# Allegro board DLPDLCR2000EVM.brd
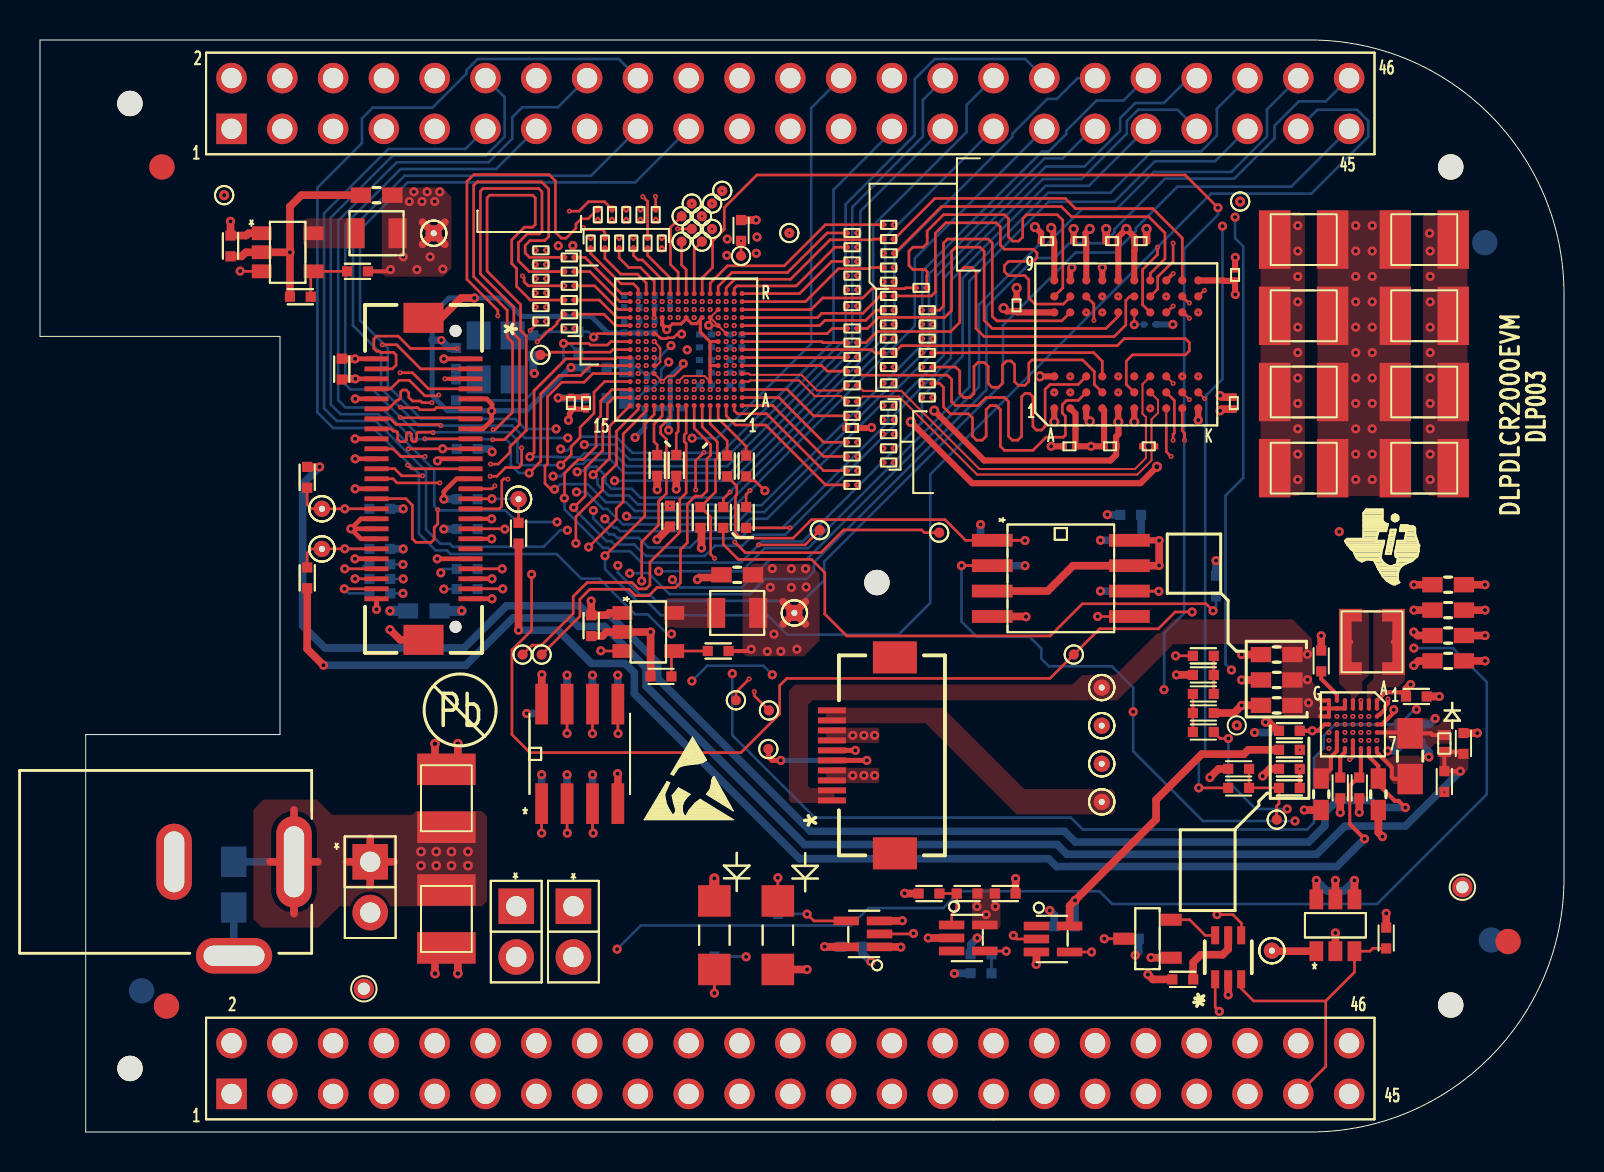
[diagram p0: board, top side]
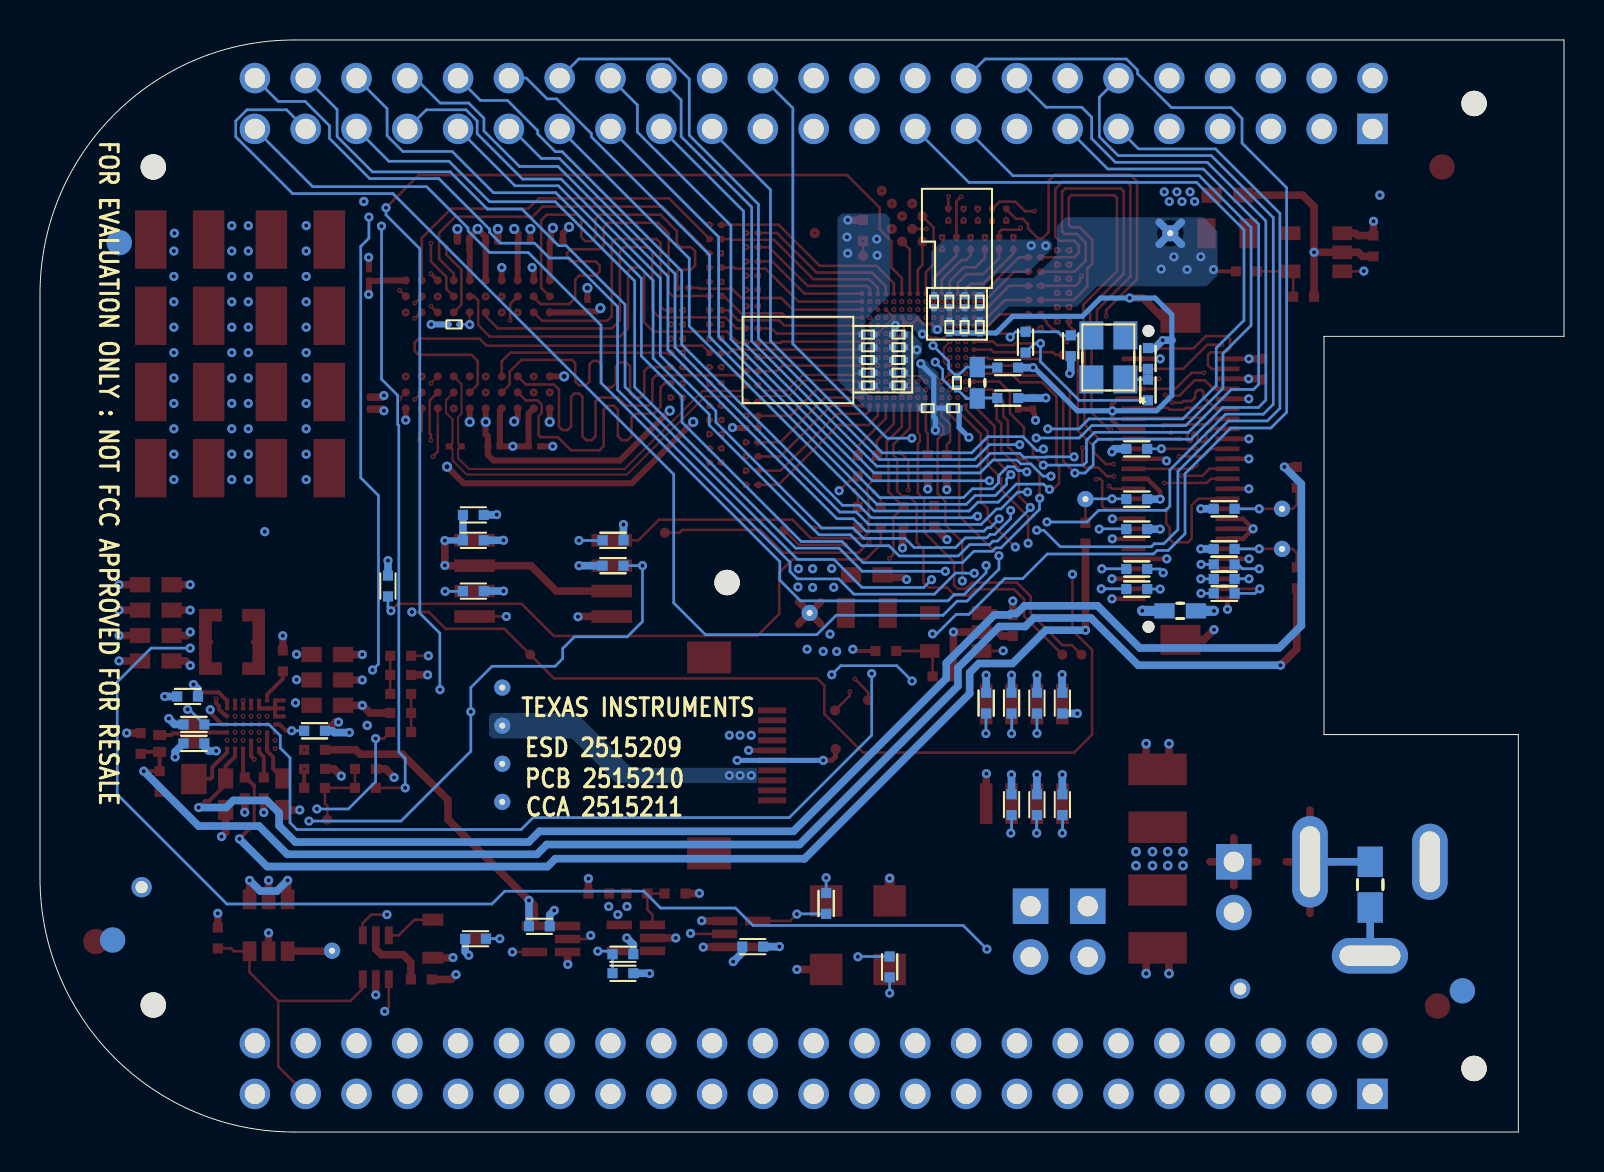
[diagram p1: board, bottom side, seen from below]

Outline 76.2 x 54.61 mm; copper layers: TOP, LY2, LY3, LY4, LY5, BOTTOM. Coordinates in mm from the lower left corner of the outline.
Outline path: 0,54.61 0,39.79 12,39.79 12,19.88 2.29,19.88 2.29,0 63.5,0 arc(72.48,3.72) 76.2,12.7 76.2,41.91 arc(72.48,50.89) 63.5,54.61 0,54.61

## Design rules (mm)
net group DMD_BUS: nets DMD_BUS DMD_BUS_T
net group DMD_D0: nets DMD_D0 DMD_D0_T
net group DMD_D1: nets DMD_D1 DMD_D1_T
net group DMD_D2: nets DMD_D2 DMD_D2_T
net group DMD_D3: nets DMD_D3 DMD_D3_T
net group DMD_D4: nets DMD_D4 DMD_D4_T
net group DMD_D5: nets DMD_D5 DMD_D5_T
net group DMD_D6: nets DMD_D6 DMD_D6_T
net group DMD_D7: nets DMD_D7 DMD_D7_T
net group DMD_D8: nets DMD_D8 DMD_D8_T
net group DMD_D9: nets DMD_D9 DMD_D9_T
net group DMD_D10: nets DMD_D10 DMD_D10_T
net group DMD_D11: nets DMD_D11 DMD_D11_T
net group DMD_D12: nets DMD_D12 DMD_D12_T
net group DMD_D13: nets DMD_D13 DMD_D13_T
net group DMD_D14: nets DMD_D14 DMD_D14_T
net group DMD_DCLK: nets DMD_DCLK DMD_DCLK_T
net group DMD_LOADB: nets DMD_LOADB DMD_LOADB_T
net group DMD_SAC_BUS: nets DMD_SAC_BUS DMD_SAC_BUS_T
net group DMD_SAC_CLK: nets DMD_SAC_CLK DMD_SAC_CLK_T
net group DMD_SCTRL: nets DMD_SCTRL DMD_SCTRL_T
net group DMD_STRB: nets DMD_STRB DMD_STRB_T
net group DMD_TRC: nets DMD_TRC DMD_TRC_T
net group MEM0_A0: nets MEM0_A0 MEM_T_A0
net group MEM0_A1: nets MEM0_A1 MEM_T_A1
net group MEM0_A2: nets MEM0_A2 MEM_T_A2
net group MEM0_A3: nets MEM0_A3 MEM_T_A3
net group MEM0_A4: nets MEM0_A4 MEM_T_A4
net group MEM0_A5: nets MEM0_A5 MEM_T_A5
net group MEM0_A6: nets MEM0_A6 MEM_T_A6
net group MEM0_A7: nets MEM0_A7 MEM_T_A7
net group MEM0_A8: nets MEM0_A8 MEM_T_A8
net group MEM0_A9: nets MEM0_A9 MEM_T_A9
net group MEM0_A10: nets MEM0_A10 MEM_T_A10
net group MEM0_A11: nets MEM0_A11 MEM_T_A11
net group MEM0_A12: nets MEM0_A12 MEM_T_A12
net group MEM0_BA0: nets MEM0_BA0 MEM_T_BA0
net group MEM0_BA1: nets MEM0_BA1 MEM_T_BA1
net group MEM0_CASZ: nets MEM0_CASZ MEM_T_CASZ
net group MEM0_CKE: nets MEM0_CKE MEM_T_CKE
net group MEM0_CLK_N: nets MEM0_CLK_N MEM_T_CLK_N
net group MEM0_CLK_P: nets MEM0_CLK_P MEM_T_CLK_P
net group MEM0_CSZ: nets MEM0_CSZ MEM_T_CSZ
net group MEM0_DQ0: nets MEM0_DQ0 MEM_T_DQ0
net group MEM0_DQ1: nets MEM0_DQ1 MEM_T_DQ1
net group MEM0_DQ2: nets MEM0_DQ2 MEM_T_DQ2
net group MEM0_DQ3: nets MEM0_DQ3 MEM_T_DQ3
net group MEM0_DQ4: nets MEM0_DQ4 MEM_T_DQ4
net group MEM0_DQ5: nets MEM0_DQ5 MEM_T_DQ5
net group MEM0_DQ6: nets MEM0_DQ6 MEM_T_DQ6
net group MEM0_DQ7: nets MEM0_DQ7 MEM_T_DQ7
net group MEM0_DQ8: nets MEM0_DQ8 MEM_T_DQ8
net group MEM0_DQ9: nets MEM0_DQ9 MEM_T_DQ9
net group MEM0_DQ10: nets MEM0_DQ10 MEM_T_DQ10
net group MEM0_DQ11: nets MEM0_DQ11 MEM_T_DQ11
net group MEM0_DQ12: nets MEM0_DQ12 MEM_T_DQ12
net group MEM0_DQ13: nets MEM0_DQ13 MEM_T_DQ13
net group MEM0_DQ14: nets MEM0_DQ14 MEM_T_DQ14
net group MEM0_DQ15: nets MEM0_DQ15 MEM_T_DQ15
net group MEM0_LDM: nets MEM0_LDM MEM_T_LDM
net group MEM0_LDQS: nets MEM0_LDQS MEM_T_LDQS
net group MEM0_RASZ: nets MEM0_RASZ MEM_T_RASZ
net group MEM0_UDM: nets MEM0_UDM MEM_T_UDM
net group MEM0_UDQS: nets MEM0_UDQS MEM_T_UDQS
net group MEM0_WEZ: nets MEM0_WEZ MEM_T_WEZ

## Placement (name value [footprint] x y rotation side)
C1  4.7uF  [0402]  9.53 44.31 90 top
C2  10uF  [0603]  16.83 46.85 180 top
C3  0.1uF  [0201]  50.36 44.55 0 top
C4  0.1uF  [0201]  51.98 44.55 0 top
C5  0.1uF  [0201]  53.61 44.55 0 top
C6  0.1uF  [0201]  55.03 44.55 180 top
C7  1uF  [0201]  59.75 42.86 270 top
C8  100uF  [1210]  63.18 44.63 180 top
C9  100uF  [1210]  69.22 44.63 0 top
C10  0.1uF  [0201]  48.83 41.34 270 top
C11  100uF  [1210]  63.18 40.82 180 top
C12  100uF  [1210]  69.22 40.82 0 top
C13  0.1uF  [0201]  26.54 36.45 90 top
C14  1uF  [0201]  27.3 36.45 90 top
C15  0.1uF  [0201]  51.47 34.29 0 top
C16  0.1uF  [0201]  53.51 34.29 180 top
C17  0.1uF  [0201]  59.69 36.45 90 top
C18  100uF  [1210]  63.18 37.01 180 top
C19  100uF  [1210]  69.22 37.01 0 top
C20  100uF  [1210]  63.18 33.2 180 top
C21  100uF  [1210]  69.22 33.2 0 top
C23  4.7uF  [0402]  27.56 25.32 90 top
C24  10uF  [0603]  34.86 27.86 180 top
C25  0.1uF  [0402_AVXA]  58.17 22.86 180 top
C26  10uF  [0603]  61.84 23.88 180 top
C27  0.1uF  [0402_AVXA]  64.06 23.56 270 top
C28  10uF  [0603]  70.41 27.37 0 top
C29  10uF  [0603]  70.41 26.1 0 top
C30  10uF  [0603]  70.41 24.83 0 top
C31  10uF  [0603]  70.41 23.56 0 top
C32  100uF  [1210]  20.32 16.69 270 top
C33  0.1uF  [0402_AVXA]  58.17 20.95 0 top
C34  10uF  [0603]  61.84 22.61 180 top
C35  10uF  [0603]  61.84 21.34 180 top
C36  1uF  [0402]  62.47 20.07 0 top
C37  0.01uF  [0402]  62.47 18.16 180 top
C38  2.2uF  [0402]  65.01 17.21 270 top
C39  1uF  [0402]  65.96 17.21 270 top
C40  1uF  [0603]  66.92 16.89 270 top
C41  0.1uF  [0402_AVXA]  68.82 21.78 0 top
C42  0.22uF  [0402]  71.17 19.43 90 top
C43  100uF  [1210]  20.32 10.66 90 top
C44  1uF  [0402]  48.26 11.93 0 top
C100  0.1uF  [0201]  34.8 39.88 180 bottom
C101  0.1uF  [0201]  34.8 39.24 180 bottom
C102  0.1uF  [0201]  33.27 39.88 0 bottom
C103  0.1uF  [0201]  33.27 39.24 0 bottom
C104  0.1uF  [0201]  31.5 41.53 270 bottom
C105  0.1uF  [0201]  30.73 41.53 270 bottom
C106  0.1uF  [0201]  30.73 40.26 90 bottom
C107  0.1uF  [0201]  29.97 41.53 270 bottom
C108  0.1uF  [0201]  29.97 40.26 90 bottom
C109  0.1uF  [0201]  29.21 41.53 270 bottom
C110  0.1uF  [0201]  29.21 40.26 90 bottom
C111  18pF  [0402]  24.66 39.32 90 bottom
C112  0.1uF  [0201]  34.8 38.61 180 bottom
C113  0.1uF  [0201]  34.8 37.97 180 bottom
C114  1uF  [0201]  34.8 37.34 180 bottom
C115  0.1uF  [0201]  33.27 38.61 0 bottom
C116  0.1uF  [0201]  33.27 37.97 0 bottom
C117  0.1uF  [0201]  33.27 37.34 0 bottom
C118  0.1uF  [0201]  31.81 36.2 180 bottom
C119  0.1uF  [0201]  30.54 36.2 0 bottom
C120  0.1uF  [0201]  30.35 37.47 270 bottom
C121  10uF  [0603]  29.34 37.47 270 bottom
C122  18pF  [0402]  20.8 38.68 90 bottom
C123  0.1uF  [0402_AVXA]  54.53 29.59 180 bottom
C124  0.1uF  [0402]  16.99 31.17 0 bottom
C125  0.1uF  [0402]  16.99 29.16 0 bottom
C126  0.1uF  [0402_AVXA]  15.09 38.15 270 top
C127  0.1uF  [0402]  21.36 31.65 180 bottom
C128  0.22uF  [0603]  19.19 26.06 180 bottom
C129  0.1uF  [0402_AVXA]  68.82 21.78 0 bottom
C130  0.1uF  [0402_AVXA]  68.5 19.43 0 bottom
C131  0.1uF  [0402_AVXA]  25.08 21.45 270 bottom
C132  0.1uF  [0402_AVXA]  51.23 10.29 180 bottom
C133  0.1uF  [0402_AVXA]  47.05 8.89 180 bottom
C134  0.1uF  [0402_AVXA]  40.56 9.27 0 bottom
D1  PMEG4002EL  [SOD882]  70.22 19.43 270 top
D2  green  [1206]  33.72 9.84 90 top
D3  green  [1206]  36.89 9.84 90 top
F100  BLM15PD800SN1D  [0402]  27.81 38.23 180 bottom
F101  BLM15PD800SN1D  [0402]  27.81 36.7 0 bottom
J1  PS-50028-05081-001  [CON_SMVT_50028-50]  19.18 32.66 270 top
J2  Pwr Jack, 2.1mm pin  [PJ-002A]  12.7 13.51 180 top
J3  HDR,2P,1R  [HDR2P_1R]  16.51 13.51 180 top
J4  HDR,2P,1R  [HDR2P_1R]  23.81 11.29 180 top
J5  HDR,2P,1R  [HDR2P_1R]  26.67 11.29 180 top
JLEDFLEX  EM,CONN,10P,ZIF  [CON_SMRT_52893-1095_NO-GND]  42.6 18.83 90 top
L1  2.2uH  [1008_2P5MMX2MM]  16.83 44.95 0 top
L2  2.2uH  [1008_2P5MMX2MM]  34.86 25.96 0 top
L3  2.2uH  [COILCRAFT_LPS3015]  66.6 24.51 180 top
L4  10uH  [0805]  68.5 18.8 90 top
NOREF  -  [unnamed]  70.54 48.26 0 top
NOREF#2  -  [#2]  32.69 17.4 0 top
NOREF#3  -  [#2]  2.29 0 90 top
NOREF#4  -  [unnamed]  6.32 6.3 0 top
NOREF#5  -  [unnamed]  4.5 3.18 0 top
NOREF#6  -  [unnamed]  6.1 48.26 0 top
NOREF#7  -  [#2]  0 54.61 0 top
NOREF#8  -  [#2]  0 54.61 0 top
NOREF#9  -  [#2]  67.16 29.51 0 top
NOREF#10  -  [#2]  -95.55 -48.74 0 top
NOREF#11  -  [unnamed]  70.54 6.35 0 top
NOREF#12  -  [#2]  -9.45 -48.23 0 top
NOREF#13  -  [unnamed]  4.5 51.44 0 top
NOREF#14  -  [#2]  2.29 0 0 top
NOREF#15  -  [#2]  2.29 0 90 top
NOREF#16  -  [#2]  96.9 37.47 0 top
NOREF#17  -  [#2]  71.96 51.38 0 top
NOREF#18  -  [#2]  2.29 0 90 top
NOREF#19  -  [unnamed]  41.85 27.48 0 top
NOREF#20  -  [#2]  2.29 0 90 top
NOREF#21  -  [#2]  2.29 0 0 top
NOREF#22  -  [unnamed]  73.41 9.53 0 top
NOREF#23  -  [unnamed]  72.57 9.6 180 bottom
NOREF#24  -  [unnamed]  5.08 7.06 180 bottom
NOREF#25  -  [unnamed]  72.24 44.48 180 bottom
P1  EM,HDR,46P,2R,2x  [PRT_12790]  9.58 50.16 90 top
P2  EM,HDR,46P,2R,2x  [PRT_12790]  9.58 1.91 90 top
R1  120k  [0402]  13.02 41.77 180 top
R2  82k  [0402]  15.88 43.04 0 top
R3  30  [0201_R]  25.04 44.09 0 top
R5  30  [0201_R]  25.04 43.38 0 top
R6  30  [0201_R]  25.04 42.67 0 top
R7  30  [0201_R]  25.04 41.96 0 top
R8  30  [0201_R]  26.47 43.74 0 top
R9  30  [0201_R]  26.47 43.03 0 top
R10  30  [0201_R]  26.47 42.32 0 top
R11  30  [0201_R]  26.47 41.61 0 top
R12  30  [0201_R]  27.53 44.45 270 top
R13  30  [0201_R]  27.89 45.87 270 top
R14  30  [0201_R]  28.24 44.45 270 top
R15  30  [0201_R]  28.6 45.87 270 top
R16  30  [0201_R]  28.96 44.45 270 top
R17  30  [0201_R]  29.31 45.87 270 top
R18  30  [0201_R]  29.67 44.45 270 top
R19  30  [0201_R]  30.02 45.87 270 top
R20  30  [0201_R]  30.38 44.45 270 top
R21  30  [0201_R]  30.78 45.87 270 top
R22  30  [0201_R]  31.09 44.45 270 top
R23  10k  [0402]  35.05 45.09 270 top
R24  30  [0201_R]  40.6 44.96 180 top
R25  30  [0201_R]  40.6 44.25 180 top
R26  30  [0201_R]  40.6 43.54 180 top
R27  30  [0201_R]  40.6 42.83 180 top
R28  30  [0201_R]  40.6 42.11 180 top
R29  30  [0201_R]  42.43 45.37 180 top
R30  30  [0201_R]  42.43 44.65 180 top
R31  30  [0201_R]  42.43 43.23 180 top
R32  30  [0201_R]  42.43 42.52 180 top
R33  30  [0201_R]  42.43 41.81 0 top
R34  30  [0201_R]  42.45 43.94 180 top
R35  30  [0201_R]  44.06 42.22 0 top
R36  30  [0201_R]  25.04 41.25 0 top
R37  30  [0201_R]  25.04 40.54 0 top
R38  30  [0201_R]  26.47 40.89 0 top
R39  30  [0201_R]  26.47 40.18 0 top
R40  30  [0201_R]  40.6 41.3 180 top
R41  30  [0201_R]  40.6 40.18 0 top
R42  30  [0201_R]  40.6 39.47 180 top
R43  30  [0201_R]  40.6 38.76 0 top
R44  30  [0201_R]  40.6 38.05 0 top
R45  30  [0201_R]  42.43 41.1 0 top
R46  30  [0201_R]  42.43 40.39 0 top
R47  30  [0201_R]  42.43 39.68 0 top
R48  30  [0201_R]  42.43 38.96 180 top
R49  30  [0201_R]  42.43 38.25 0 top
R50  30  [0201_R]  44.36 41.1 0 top
R51  30  [0201_R]  44.36 40.39 0 top
R52  30  [0201_R]  44.36 39.68 0 top
R53  30  [0201_R]  44.36 38.96 0 top
R54  30  [0201_R]  44.36 38.25 0 top
R55  30  [0201_R]  40.6 37.34 180 top
R56  30  [0201_R]  40.6 36.53 180 top
R57  30  [0201_R]  40.6 35.82 180 top
R58  10k  [0201]  40.6 35.21 0 top
R59  30  [0201_R]  40.6 34.49 180 top
R60  30  [0201_R]  42.43 37.44 0 top
R61  30  [0201_R]  42.43 36.32 0 top
R62  30  [0201_R]  42.43 35.61 180 top
R63  30  [0201_R]  42.43 34.9 180 top
R64  30  [0201_R]  42.43 34.19 180 top
R65  30  [0201_R]  44.36 37.44 0 top
R66  30  [0201_R]  44.36 36.73 0 top
R67  100  [0201]  55.44 34.29 180 top
R68  0  [0402]  13.36 32.74 270 top
R69  0  [0402]  13.36 27.71 90 top
R70  100k  [0402]  30.86 33.34 90 top
R71  10k  [0402]  31.5 30.8 270 top
R72  30.1  [0402]  31.81 33.34 270 top
R74  100k  [0402]  33.02 30.73 90 top
R75  30.1  [0402]  34.16 30.73 90 top
R76  30.1  [0402]  34.36 33.31 90 top
R77  30.1  [0402]  35.31 30.73 90 top
R78  30.1  [0402]  35.31 33.31 90 top
R79  30  [0201_R]  40.6 33.78 180 top
R80  30  [0201_R]  40.6 33.07 180 top
R81  30  [0201_R]  40.6 32.36 180 top
R82  30  [0201_R]  42.43 33.48 180 top
R83  180k  [0402]  31.05 22.78 180 top
R84  360k  [0402]  33.91 24.05 0 top
R85  1K  [0402]  58.17 23.81 0 top
R86  1K  [0402]  58.17 21.91 180 top
R87  1K  [0402]  58.17 20 0 top
R89  30.0k  [0402]  59.93 17.21 180 top
R90  0  [0402]  62.47 19.11 0 top
R91  0  [0402]  62.47 17.21 0 top
R92  0.10  [0603]  64.06 16.89 270 top
R93  100k  [0402]  70.22 17.53 270 top
R94  887k  [0402]  44.45 11.93 0 top
R95  953k  [0402]  46.36 11.93 0 top
R96  0  [0402]  57.14 7.63 180 top
R97  10k  [0402]  67.31 9.7 90 top
R100  30  [0201_R]  55.5 40.39 0 bottom
R101  953k  [0402]  26.92 39.5 270 bottom
R102  100  [0402]  20.8 37.11 90 bottom
R103  0  [0402]  54.53 30.86 0 bottom
R104  100k  [0402]  47.55 29.59 0 bottom
R105  0  [0402]  16.99 28.38 0 bottom
R106  0  [0402]  16.99 27.66 0 bottom
R107  0  [0402]  23.93 29.95 90 top
R108  100k  [0402]  21.36 30.15 180 bottom
R109  100k  [0402]  21.36 34.16 0 bottom
R110  100k  [0402]  58.8 27.3 270 bottom
R111  100k  [0402]  54.53 27.05 0 bottom
R112  100k  [0402]  47.55 28.32 180 bottom
R113  0  [0402]  16.99 26.94 0 bottom
R114  0  [0402]  21.36 28.16 0 bottom
R115  0  [0402]  21.36 27.15 0 bottom
R116  100k  [0402]  68.5 20.38 180 bottom
R117  0  [0402]  62.47 20.07 0 bottom
R118  5.6K  [0402]  28.89 21.45 90 bottom
R119  5.6K  [0402]  27.62 21.45 90 bottom
R120  0  [0402]  26.35 21.45 90 bottom
R121  4.75K  [0402]  27.62 16.37 90 bottom
R122  4.75K  [0402]  26.35 16.37 90 bottom
R123  4.75K  [0402]  25.08 16.37 90 bottom
R124  200  [0805]  9.69 12.37 270 bottom
R125  1K  [0402]  54.42 9.66 0 bottom
R126  100  [0402]  36.89 11.43 270 bottom
R128  0  [0402]  47.05 7.94 180 bottom
R129  100  [0402]  33.72 8.26 90 bottom
RT1  100k  [0402]  59.93 18.16 180 top
TP1  TP,20mil PAD  [20MIL_PAD]  9.21 46.85 0 top
TP2  TP,12mil Drill,32mil Pad  [HOLE_PLATED_12MIL_DRILL_32MIL_PAD]  19.69 44.95 0 top
TP3  TP,20mil PAD  [20MIL_PAD]  32.08 45.8 90 top
TP4  TP,20mil PAD  [20MIL_PAD]  32.08 44.53 90 top
TP5  TP,20mil PAD  [20MIL_PAD]  32.59 46.43 90 top
TP6  TP,20mil PAD  [20MIL_PAD]  32.59 45.16 90 top
TP7  TP,20mil PAD  [20MIL_PAD]  33.1 45.8 90 top
TP8  TP,20mil PAD  [20MIL_PAD]  33.1 44.53 90 top
TP9  TP,20mil PAD  [20MIL_PAD]  33.6 46.43 90 top
TP10  TP,20mil PAD  [20MIL_PAD]  33.6 45.16 90 top
TP11  TP,20mil PAD  [20MIL_PAD]  34.11 47.07 90 top
TP12  TP,20mil PAD  [20MIL_PAD]  35.05 43.81 90 top
TP13  TP,20mil PAD  [20MIL_PAD]  37.47 44.96 90 top
TP14  TP,20mil PAD  [20MIL_PAD]  60.01 46.53 0 top
TP15  TP,20mil PAD  [20MIL_PAD]  25.02 38.86 90 top
TP16  TP,12mil Drill,32mil Pad  [HOLE_PLATED_12MIL_DRILL_32MIL_PAD]  23.93 31.65 0 top
TP17  TP,12mil Drill,32mil Pad  [HOLE_PLATED_12MIL_DRILL_32MIL_PAD]  14.1 31.17 0 top
TP18  TP,12mil Drill,32mil Pad  [HOLE_PLATED_12MIL_DRILL_32MIL_PAD]  14.1 29.16 0 top
TP19  TP,20mil PAD  [20MIL_PAD]  38.99 30.1 0 top
TP20  TP,20mil PAD  [20MIL_PAD]  44.96 29.97 0 top
TP21  TP,20mil PAD  [20MIL_PAD]  24.13 23.88 0 top
TP22  TP,20mil PAD  [20MIL_PAD]  25.08 23.88 0 top
TP23  TP,12mil Drill,32mil Pad  [HOLE_PLATED_12MIL_DRILL_32MIL_PAD]  37.72 25.96 0 top
TP24  TP,20mil PAD  [20MIL_PAD]  51.69 23.88 90 top
TP25  TP,20mil PAD  [20MIL_PAD]  34.8 21.59 0 top
TP26  TP,20mil PAD  [20MIL_PAD]  36.42 19.15 180 top
TP27  TP,20mil PAD  [20MIL_PAD]  36.45 21.08 0 top
TP28  TP,12mil Drill,32mil Pad  [HOLE_PLATED_12MIL_DRILL_32MIL_PAD]  53.09 22.23 180 top
TP29  TP,12mil Drill,32mil Pad  [HOLE_PLATED_12MIL_DRILL_32MIL_PAD]  53.09 20.32 180 top
TP30  TP,12mil Drill,32mil Pad  [HOLE_PLATED_12MIL_DRILL_32MIL_PAD]  53.09 18.41 180 top
TP31  TP,12mil Drill,32mil Pad  [HOLE_PLATED_12MIL_DRILL_32MIL_PAD]  53.09 16.51 180 top
TP32  TP,20mil PAD  [20MIL_PAD]  59.84 20.34 0 top
TP33  TP,20mil PAD  [20MIL_PAD]  61.84 15.62 270 top
TP34  TP,12mil Drill,32mil Pad  [HOLE_PLATED_12MIL_DRILL_32MIL_PAD]  61.59 9.07 0 top
TPGND1  -  [TP40]  16.19 7.16 0 top
TPGND2  -  [TP40]  71.12 12.24 0 top
U1  TPS62260DDCT  [TSOT-23_DDC_R-PDSO-G5]  12.38 43.99 270 top
U2  TPS62260DDCT  [TSOT-23_DDC_R-PDSO-G5]  30.42 25.01 270 top
U3  W25Q16DW  [W25Q16DW_WINBOND]  51.04 27.69 270 top
U4  CAT24C256W  [8-SOIC]  26.99 18.91 0 top
U5  TIDLP,PAD1000  [PAD1000]  65.65 20.38 270 top
U6  SN74LVC1G125DCK  [U_5_DCK]  41.2 9.91 270 top
U7  TPS71501DCK  [U_5_DCK]  46.36 9.7 90 top
U8  LOG,INV,OPENDRN,SN74AUP1G06DCK  [U_5_DCK]  50.6 9.65 90 top
U9  -  [TLV809I50]  55.37 9.66 90 top
U10  SN74LVC1G3208  [DCK_PDSO_6]  59.41 8.74 90 top
U11  TPS22929DDBVT  [SOT23-6_DBV_R-PDSO-G6]  64.77 10.34 0 top
U12  DLPC2607  [DPP2607]  32.31 39.13 180 top
U13  MT46H32M16_FBGA_60P  [VFBGA_60]  54.31 39.39 90 top
XD100  16.66667MHz  [4_SMD]  22.78 38.73 90 bottom

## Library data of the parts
C1-C21 C23-C44 C100-C134 = PAS,CAP,NP,large
D1 = PAS,DIODE,SCHOTTKY,large
D2 D3 = PAS,DIODE,LED,large
F100 F101 = PAS,FERRITE BEAD,3
J1 = EM,CONN,50P,2R,90deg_0
J2 = EM,CONN,PWRJACK,RAPC712X_0: User Part Number: X; Tolerance: X
J3-J5 = EM,HDR,2P,1R,2x
JLEDFLEX = EM,CONN,10P,ZIF
L1-L4 = PAS,INDUCTOR, large
P1 P2 = EM,HDR,46P,2R,2x
R1 R2 R23 R58 R67-R72 R74-R78 R83-R87 R89-R97 R101-R126 R128 R129 = PAS,R,large
R3 R5-R22 R24-R57 R59-R66 R79-R82 R100 = PAS,R,large: signal model: PAS_R_LARGE_0201_R_30_30
RT1 = PAS,THERMISTOR,large
TP1-TP34 TPGND1 TPGND2 = EM,TERM,TESTPOINT
U1 U2 = PWR,REG,TPS62260,TSOT23_DDC
U3 = W25Q16DW
U4 = MEM,EEPROM,CAT24C256
U5 = TIDLP,PAD1000_0
U6 = LOG,BUF,SN74LVC1G125DCK
U7 = TPS71501DCK
U8 = LOG,INV,OPENDRN,SN74AUP1G06DCK
U9 = PWR,MON,TLV809I50
U10 = LOG,SN74LVC1G3208_2
U11 = PWR,SW,TPS22929DDBV
U12 = TIDLP,DPP2607
U13 = MEM,SDRAM,64x16,BGA_60P
XD100 = XTAL_NX3225GA

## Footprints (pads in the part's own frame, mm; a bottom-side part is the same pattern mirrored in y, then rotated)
4_SMD
  rect 1.4x1.2 smd: 1(-1.1,-0.85) 2(1.1,-0.85) 3(1.1,0.85) 4(-1.1,0.85)
8-SOIC
  rect 0.635x2.032 smd: 1(-1.905,-2.489) 2(-0.635,-2.489) 3(0.635,-2.489) 4(1.905,-2.489) 5(1.905,2.489) 6(0.635,2.489) 7(-0.635,2.489) 8(-1.905,2.489)
20MIL_PAD
  round 0.508 smd: 1(0,0)
0201
  rect 0.356x0.305 smd: 1(0.3,0) 2(-0.3,0)
0201_R
  custom 0.083x0.083 smd: 1(-0.279,0) 2(0.279,0)
0402
  rect 0.508x0.508 smd: 1(-0.521,0) 2(0.521,0)
0402_AVXA
  rect 0.508x0.508 smd: 1(-0.521,0) 2(0.521,0)
0603
  rect 1.016x0.762 smd: 1(-0.787,0) 2(0.787,0)
0805
  rect 1.524x1.27 smd: 1(-1.143,0) 2(1.143,0)
1008_2P5MMX2MM
  rect 0.9x1.5 smd: 1(-1.05,0) 2(1.05,0)
1206
  rect 1.575x1.626 smd: 1(-1.714,0) 2(1.714,0)
1210
  rect 1.575x2.921 smd: 1(1.448,0) 2(-1.448,0)
COILCRAFT_LPS3015
  custom 0.286x0.286 smd: 1(1.079,0) 2(-1.079,0)
CON_SMRT_52893-1095_NO-GND
  rect 1.6x2.2 smd: (-4.9,-0.15) (4.9,-0.15)
  rect 0.3x1.4 smd: 1(-2.25,3) 2(-1.75,3) 3(-1.25,3) 4(-0.75,3) 5(-0.25,3) 6(0.25,3) 7(0.75,3) 8(1.25,3) 9(1.75,3) 10(2.25,3)
CON_SMVT_50028-50
  round 0.6 hole 0.6 unplated: (-7.4,1.6) (7.4,1.6)
  rect 0.24x1.2 smd: 1(-6,2.35) 2(-6,-2.35) 3(-5.5,2.35) 4(-5.5,-2.35) 5(-5,2.35) 6(-5,-2.35) 7(-4.5,2.35) 8(-4.5,-2.35) 9(-4,2.35) 10(-4,-2.35) 11(-3.5,2.35) 12(-3.5,-2.35) 13(-3,2.35) 14(-3,-2.35) 15(-2.5,2.35) 16(-2.5,-2.35) 17(-2,2.35) 18(-2,-2.35) 19(-1.5,2.35) 20(-1.5,-2.35) 21(-1,2.35) 22(-1,-2.35) 23(-0.5,2.35) 24(-0.5,-2.35) 25(0,2.35) 26(0,-2.35) 27(0.5,2.35) 28(0.5,-2.35) 29(1,2.35) 30(1,-2.35) 31(1.5,2.35) 32(1.5,-2.35) 33(2,2.35) 34(2,-2.35) 35(2.5,2.35) 36(2.5,-2.35) 37(3,2.35) 38(3,-2.35) 39(3.5,2.35) 40(3.5,-2.35) 41(4,2.35) 42(4,-2.35) 43(4.5,2.35) 44(4.5,-2.35) 45(5,2.35) 46(5,-2.35) 47(5.5,2.35) 48(5.5,-2.35) 49(6,2.35) 50(6,-2.35)
  rect 1.5x2 smd: 51(-8.05,0) 52(8.05,0)
DCK_PDSO_6
  rect 0.9x0.4 smd: 1(-1.1,0.65) 2(-1.1,0) 3(-1.1,-0.65) 4(1.1,-0.65) 5(1.1,0) 6(1.1,0.65)
DPP2607
  round 0.254 smd: A1(-2.8,2.8) A2(-2.4,2.8) A3(-2,2.8) A4(-1.6,2.8) A5(-1.2,2.8) A6(-0.8,2.8) A7(-0.4,2.8) A8(0,2.8) A9(0.4,2.8) A10(0.8,2.8) A11(1.2,2.8) A12(1.6,2.8) A13(2,2.8) A14(2.4,2.8) A15(2.8,2.8) B1(-2.8,2.4) B2(-2.4,2.4) B3(-2,2.4) B4(-1.6,2.4) B5(-1.2,2.4) B6(-0.8,2.4) B7(-0.4,2.4) B8(0,2.4) B9(0.4,2.4) B10(0.8,2.4) B11(1.2,2.4) B12(1.6,2.4) B13(2,2.4) B14(2.4,2.4) B15(2.8,2.4) C1(-2.8,2) C2(-2.4,2) C3(-2,2) C4(-1.6,2) C5(-1.2,2) C6(-0.8,2) C7(-0.4,2) C8(0,2) C9(0.4,2) C10(0.8,2) C11(1.2,2) C12(1.6,2) C13(2,2) C14(2.4,2) C15(2.8,2) D1(-2.8,1.6) D2(-2.4,1.6) D3(-2,1.6) D4(-1.6,1.6) D5(-1.2,1.6) D6(-0.8,1.6) D7(-0.4,1.6) D8(0,1.6) D9(0.4,1.6) D10(0.8,1.6) D11(1.2,1.6) D12(1.6,1.6) D13(2,1.6) D14(2.4,1.6) D15(2.8,1.6) E1(-2.8,1.2) E2(-2.4,1.2) E3(-2,1.2) E4(-1.6,1.2) E12(1.6,1.2) E13(2,1.2) E14(2.4,1.2) E15(2.8,1.2) F1(-2.8,0.8) F2(-2.4,0.8) F3(-2,0.8) F4(-1.6,0.8) F12(1.6,0.8) F13(2,0.8) F14(2.4,0.8) F15(2.8,0.8) G1(-2.8,0.4) G2(-2.4,0.4) G3(-2,0.4) G4(-1.6,0.4) G12(1.6,0.4) G13(2,0.4) G14(2.4,0.4) G15(2.8,0.4) H1(-2.8,0) H2(-2.4,0) H3(-2,0) H4(-1.6,0) H12(1.6,0) H13(2,0) H14(2.4,0) H15(2.8,0) J1(-2.8,-0.4) J2(-2.4,-0.4) J3(-2,-0.4) J4(-1.6,-0.4) J12(1.6,-0.4) J13(2,-0.4) J14(2.4,-0.4) J15(2.8,-0.4) K1(-2.8,-0.8) K2(-2.4,-0.8) K3(-2,-0.8) K4(-1.6,-0.8) K12(1.6,-0.8) K13(2,-0.8) K14(2.4,-0.8) K15(2.8,-0.8) L1(-2.8,-1.2) L2(-2.4,-1.2) L3(-2,-1.2) L4(-1.6,-1.2) L12(1.6,-1.2) L13(2,-1.2) L14(2.4,-1.2) L15(2.8,-1.2) M1(-2.8,-1.6) M2(-2.4,-1.6) M3(-2,-1.6) M4(-1.6,-1.6) M5(-1.2,-1.6) M6(-0.8,-1.6) M7(-0.4,-1.6) M8(0,-1.6) M9(0.4,-1.6) M10(0.8,-1.6) M11(1.2,-1.6) M12(1.6,-1.6) M13(2,-1.6) M14(2.4,-1.6) M15(2.8,-1.6) N1(-2.8,-2) N2(-2.4,-2) N3(-2,-2) N4(-1.6,-2) N5(-1.2,-2) N6(-0.8,-2) N7(-0.4,-2) N8(0,-2) N9(0.4,-2) N10(0.8,-2) N11(1.2,-2) N12(1.6,-2) N13(2,-2) N14(2.4,-2) N15(2.8,-2) P1(-2.8,-2.4) P2(-2.4,-2.4) P3(-2,-2.4) P4(-1.6,-2.4) P5(-1.2,-2.4) P6(-0.8,-2.4) P7(-0.4,-2.4) P8(0,-2.4) P9(0.4,-2.4) P10(0.8,-2.4) P11(1.2,-2.4) P12(1.6,-2.4) P13(2,-2.4) P14(2.4,-2.4) P15(2.8,-2.4) R1(-2.8,-2.8) R2(-2.4,-2.8) R3(-2,-2.8) R4(-1.6,-2.8) R5(-1.2,-2.8) R6(-0.8,-2.8) R7(-0.4,-2.8) R8(0,-2.8) R9(0.4,-2.8) R10(0.8,-2.8) R11(1.2,-2.8) R12(1.6,-2.8) R13(2,-2.8) R14(2.4,-2.8) R15(2.8,-2.8)
HDR2P_1R
  rect 1.778x1.778 hole 1.016: 1(0,0)
  round 1.778 hole 1.016: 2(0,2.54)
HOLE_PLATED_12MIL_DRILL_32MIL_PAD
  round 0.813 hole 0.305: 1(0,0)
PAD1000
  round 0.229 smd: A1(-1.2,1.2) A2(-0.8,1.2) A3(-0.4,1.2) A4(0,1.2) A5(0.4,1.2) A6(0.8,1.2) A7(1.2,1.2) B1(-1.2,0.8) B2(-0.8,0.8) B3(-0.4,0.8) B4(0,0.8) B5(0.4,0.8) B6(0.8,0.8) B7(1.2,0.8) C1(-1.2,0.4) C2(-0.8,0.4) C3(-0.4,0.4) C4(0,0.4) C5(0.4,0.4) C6(0.8,0.4) C7(1.2,0.4) D1(-1.2,0) D2(-0.8,0) D3(-0.4,0) D4(0,0) D5(0.4,0) D6(0.8,0) D7(1.2,0) E1(-1.2,-0.4) E2(-0.8,-0.4) E3(-0.4,-0.4) E4(0,-0.4) E5(0.4,-0.4) E6(0.8,-0.4) E7(1.2,-0.4) F1(-1.2,-0.8) F2(-0.8,-0.8) F3(-0.4,-0.8) F4(0,-0.8) F5(0.4,-0.8) F6(0.8,-0.8) F7(1.2,-0.8) G1(-1.2,-1.2) G2(-0.8,-1.2) G3(-0.4,-1.2) G4(0,-1.2) G5(0.4,-1.2) G6(0.8,-1.2) G7(1.2,-1.2)
PJ-002A
  oval 1.778x4.572 hole 1.016x3.556: 1(0,0)
  oval 1.778x3.81 hole 1.016x3.048: 2(5.994,0)
  oval 3.81x1.778 hole 3.048x1.016: 3(2.997,4.699)
PRT_12790
  rect 1.524x1.524 hole 1.016: 1(0,0)
  round 1.524 hole 1.016: 2(2.54,0) 3(0,-2.54) 4(2.54,-2.54) 5(0,-5.08) 6(2.54,-5.08) 7(0,-7.62) 8(2.54,-7.62) 9(0,-10.16) 10(2.54,-10.16) 11(0,-12.7) 12(2.54,-12.7) 13(0,-15.24) 14(2.54,-15.24) 15(0,-17.78) 16(2.54,-17.78) 17(0,-20.32) 18(2.54,-20.32) 19(0,-22.86) 20(2.54,-22.86) 21(0,-25.4) 22(2.54,-25.4) 23(0,-27.94) 24(2.54,-27.94) 25(0,-30.48) 26(2.54,-30.48) 27(0,-33.02) 28(2.54,-33.02) 29(0,-35.56) 30(2.54,-35.56) 31(0,-38.1) 32(2.54,-38.1) 33(0,-40.64) 34(2.54,-40.64) 35(0,-43.18) 36(2.54,-43.18) 37(0,-45.72) 38(2.54,-45.72) 39(0,-48.26) 40(2.54,-48.26) 41(0,-50.8) 42(2.54,-50.8) 43(0,-53.34) 44(2.54,-53.34) 45(0,-55.88) 46(2.54,-55.88)
SOD882
  rect 0.5x0.65 smd: 1(-0.421,0) 2(0.421,0)
SOT23-6_DBV_R-PDSO-G6
  rect 0.686x0.991 smd: 1(-0.953,-1.295) 2(0,-1.295) 3(0.953,-1.295) 4(0.953,1.295) 5(0,1.295) 6(-0.953,1.295)
TLV809I50
  rect 0.6x1.05 smd: 1(-0.95,-1.185) 2(0.95,-1.185) 3(0,1.185)
TP40
  round 1.016 hole 0.61: 1(0,0)
TSOT-23_DDC_R-PDSO-G5
  rect 0.686x0.991 smd: 1(-0.953,-1.295) 2(0,-1.295) 3(0.953,-1.295) 4(0.953,1.295) 5(-0.953,1.295)
U_5_DCK
  rect 0.432x1.27 smd: 1(0.65,0.775) 2(0,0.775) 3(-0.65,0.775) 4(-0.65,-0.884) 5(0.65,-0.884)
unnamed
  round 1.27 hole 3.175 unplated: (0,0)
VFBGA_60
  round 0.406 smd: A1(-3.2,3.6) A2(-2.4,3.6) A3(-1.6,3.6) A7(1.6,3.6) A8(2.4,3.6) A9(3.2,3.6) B1(-3.2,2.8) B2(-2.4,2.8) B3(-1.6,2.8) B7(1.6,2.8) B8(2.4,2.8) B9(3.2,2.8) C1(-3.2,2) C2(-2.4,2) C3(-1.6,2) C7(1.6,2) C8(2.4,2) C9(3.2,2) D1(-3.2,1.2) D2(-2.4,1.2) D3(-1.6,1.2) D7(1.6,1.2) D8(2.4,1.2) D9(3.2,1.2) E1(-3.2,0.4) E2(-2.4,0.4) E3(-1.6,0.4) E7(1.6,0.4) E8(2.4,0.4) E9(3.2,0.4) F1(-3.2,-0.4) F2(-2.4,-0.4) F3(-1.6,-0.4) F7(1.6,-0.4) F8(2.4,-0.4) F9(3.2,-0.4) G1(-3.2,-1.2) G2(-2.4,-1.2) G3(-1.6,-1.2) G7(1.6,-1.2) G8(2.4,-1.2) G9(3.2,-1.2) H1(-3.2,-2) H2(-2.4,-2) H3(-1.6,-2) H7(1.6,-2) H8(2.4,-2) H9(3.2,-2) J1(-3.2,-2.8) J2(-2.4,-2.8) J3(-1.6,-2.8) J7(1.6,-2.8) J8(2.4,-2.8) J9(3.2,-2.8) K1(-3.2,-3.6) K2(-2.4,-3.6) K3(-1.6,-3.6) K7(1.6,-3.6) K8(2.4,-3.6) K9(3.2,-3.6)
W25Q16DW_WINBOND
  rect 0.635x2.032 smd: 1(-1.905,-3.429) 2(-0.635,-3.429) 3(0.635,-3.429) 4(1.905,-3.429) 5(1.905,3.429) 6(0.635,3.429) 7(-0.635,3.429) 8(-1.905,3.429)

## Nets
DGND: C1.1(P) C2.2(N) C3.2(N) C4.2(N) C5.2(N) C6.2(N) C7.2(N) C8.1(P) C9.1(P) C10.2(N) C11.1(P) C12.1(P) C13.2(N) C14.2(N) C15.2(N) C16.2(N) C17.2(N) C18.1(P) C19.1(P) C20.1(P) C21.1(P) C23.1(P) C24.2(N) C25.2(N) C26.2(N) C27.1(P) C28.2(N) C29.2(N) C30.2(N) C31.2(N) C32.2(N) C33.2(N) C34.2(N) C35.2(N) C36.1(P) C37.2(N) C38.2(N) C39.2(N) C40.2(N) C41.2(N) C42.2(N) C43.2(N) C44.2(N) C100.2(N) C101.2(N) C102.2(N) C103.2(N) C104.2(N) C105.2(N) C106.2(N) C107.2(N) C108.2(N) C109.2(N) C110.2(N) C111.1(P) C112.2(N) C113.2(N) C114.2(N) C115.2(N) C116.2(N) C117.2(N) C118.2(N) C119.2(N) C122.2(N) C123.2(N) C124.2(N) C125.2(N) C126.2(N) C127.2(N) C128.2(N) C129.2(N) C130.2(N) C131.2(N) C132.2(N) C133.2(N) C134.2(N) D3.1(P1) F100.2(N2) J1.5(P5) J1.6(P6) J1.9(P9) J1.10(P10) J1.15(P15) J1.18(P18) J1.25(P25) J1.28(P28) J1.33(P33) J1.34(P34) J1.36(P36) J1.37(P37) J1.38(P38) J1.45(P45) J1.49(P49) J1.50(P50) J1.51(P51) J1.52(P52) J2.2(SLEEVE) J3.2 J4.1 J5.1 JLEDFLEX.6(P6) P1.1(P1) P1.2(P2) P2.1(P1) P2.2(P2) P2.44(P44) P2.45(P45) P2.46(P46) R1.2(N2) R23.1(N1) R58.1(N1) R72.2(N2) R74.1(N1) R83.2(N2) R92.2(N2) R94.1(N1) R100.2(N2) R111.1(N1) R112.1(N1) RT1.2 TP1.1(P1) TP14.1(P1) TPGND1.1(P1) TPGND2.1(P1) U1.2(GND) U2.2(GND) U3.4(GND) U4.4(GND) U5.A3(AGND1) U5.A6(PGNDR) U5.C1(PGNDL_1) U5.C2(PGNDL_2) U5.D6(DGND) U5.D7(AGND) U6.1(OEZ) U6.3(GND) U7.2(GND) U8.3(GND) U9.1(GND) U10.2(GND) U11.2(GND#2) U11.5(GND#5) U12.D4(VSS#D4) U12.D7(VSS#D7) U12.D10(VSS#D10) U12.D12(VSS#D12) U12.G4(VSS#G4) U12.G12(VSS#G12) U12.H4(VSS#H4) U12.K4(VSS#K4) U12.L12(VSS#L12) U12.M4(VSS#M4) U12.M7(VSS#M7) U12.M10(VSS#M10) U13.A1(VSS#A1) U13.A3(VSSQ#A3) U13.B9(VSSQ#B9) U13.C1(VSSQ#C1) U13.D9(TEST) U13.E1(VSSQ#E1) U13.F1(VSS#F1) U13.K1(VSS#K1)
V2V5: C38.1(P) U5.E7(V2V5)
V6V: C27.2(N) U5.F1(V6V)
VDD_PLL: C120.1(P) C121.2(N) F101.2(N2) U12.H12(VDD_PLL)
VINA: C36.2(N) R117.2(N2) U5.G4(VINA)
VINTF: C118.1(P) C119.1(P) C131.1(P) P2.3(P3) R118.2(N2) R119.2(N2) R120.2(N2) R121.2(N2) R122.2(N2) R123.2(N2) TP34.1(P1) U4.8(VCC) U11.1(VOUT) U12.D11(VCC_INTF#D11) U12.E12(VCC_INTF#E12)
VSS_PLL: C120.2(N) C121.1(P) F100.1(N1) U12.J13(VSS_PLL)
B[0]: P1.19(P19) U12.G14(PDATA_0)
B[1]: P1.17(P17) U12.G13(PDATA_1)
B[2]: P1.16(P16) U12.F15(PDATA_2)
B[3]: P1.34(P34) U12.F14(PDATA_3)
B[4]: P1.35(P35) U12.F13(PDATA_4)
B[5]: P1.33(P33) U12.E15(PDATA_5)
B[6]: P1.31(P31) U12.E14(PDATA_6)
B[7]: P1.32(P32) U12.E13(PDATA_7)
BLU_CATHODE: JLEDFLEX.9(P9) JLEDFLEX.10(P10) TP31.1(P1) U5.G7(SW6)
CMP_OUT: R74.2(N2) U5.D4(CMP_OUT) U12.A6(CMP_OUT)
CMP_PWM_F: C25.1(P) R85.2(N2) R86.1(N1)
CMP_PWM_F2: C33.1(P) R86.2(N2) R87.1(N1)
CMP_PWR: R89.2(N2) U12.P5(GPIO0_CMPPWR)
DATEN: P1.30(P30) U12.G15(DATEN_CMD)
DBIC_CSZ: R71.1(N1) U12.B10(DBIC_CSZ)
DMD_BUS: J1.27(P27) R37.1(N1)
DMD_BUS_T: R37.2(N2) U12.L13(DMD_DAD_BUS)
DMD_D0: J1.26(P26) R11.1(N1)
DMD_D0_T: R11.2(N2) U12.M15(DMD_D0)
DMD_D1: J1.4(P4) R6.1(N1)
DMD_D1_T: R6.2(N2) U12.N14(DMD_D1)
DMD_D2: J1.8(P8) R7.1(N1)
DMD_D2_T: R7.2(N2) U12.M14(DMD_D2)
DMD_D3: J1.12(P12) R10.1(N1)
DMD_D3_T: R10.2(N2) U12.N15(DMD_D3)
DMD_D4: J1.14(P14) R13.1(N1)
DMD_D4_T: R13.2(N2) U12.P13(DMD_D4)
DMD_D5: J1.16(P16) R5.1(N1)
DMD_D5_T: R5.2(N2) U12.P14(DMD_D5)
DMD_D6: J1.24(P24) R9.1(N1)
DMD_D6_T: R9.2(N2) U12.P15(DMD_D6)
DMD_D7: J1.20(P20) R8.1(N1)
DMD_D7_T: R8.2(N2) U12.R15(DMD_D7)
DMD_D8: J1.7(P7) R16.1(N1)
DMD_D8_T: R16.2(N2) U12.R12(DMD_D8)
DMD_D9: J1.3(P3) R19.1(N1)
DMD_D9_T: R19.2(N2) U12.N11(DMD_D9)
DMD_D10: J1.13(P13) R17.1(N1)
DMD_D10_T: R17.2(N2) U12.P11(DMD_D10)
DMD_D11: J1.11(P11) R18.1(N1)
DMD_D11_T: R18.2(N2) U12.R11(DMD_D11)
DMD_D12: R22.1(N1) R105.2(N2)
DMD_D12_OPT: J1.44(P44) R105.1(N1)
DMD_D12_T: R22.2(N2) U12.N10(DMD_D12)
DMD_D13: R21.1(N1) R106.2(N2)
DMD_D13_OPT: J1.46(P46) R106.1(N1)
DMD_D13_T: R21.2(N2) U12.P10(DMD_D13)
DMD_D14: R20.1(N1) R113.2(N2)
DMD_D14_OPT: J1.48(P48) R113.1(N1)
DMD_D14_T: R20.2(N2) U12.R10(DMD_D14)
DMD_DCLK: J1.17(P17) R3.1(N1)
DMD_DCLK_T: R3.2(N2) U12.N13(DMD_DCLK)
DMD_LOADB: J1.19(P19) R14.1(N1) R109.1(N1)
DMD_LOADB_T: R14.2(N2) U12.R13(DMD_LOADB)
DMD_OEZ: J1.35(P35) R108.1(N1) U12.M13(DMD_DAD_OEZ)
DMD_SAC_BUS: J1.31(P31) R38.1(N1)
DMD_SAC_BUS_T: R38.2(N2) U12.L15(DMD_SAC_BUS)
DMD_SAC_CLK: R36.1(N1) R114.1(N1)
DMD_SAC_CLK_OPT: J1.43(P43) R114.2(N2)
DMD_SAC_CLK_T: R36.2(N2) U12.L14(DMD_SAC_CLK)
DMD_SCTRL: J1.23(P23) R12.1(N1)
DMD_SCTRL_T: R12.2(N2) U12.R14(DMD_SCTRL)
DMD_STRB: J1.30(P30) R39.1(N1)
DMD_STRB_T: R39.2(N2) U12.K13(DMD_DAD_STRB)
DMD_TRC: R15.1(N1) R115.1(N1)
DMD_TRC_OPT: J1.47(P47) R115.2(N2)
DMD_TRC_T: R15.2(N2) U12.P12(DMD_TRC)
DMD_VBIAS: C124.1(P) J1.32(P32) R68.2(N2) TP17.1(P1)
DMD_VOFS: C127.1(P) J1.29(P29) R107.2(N2) TP16.1(P1)
DMD_VRST: C125.1(P) J1.40(P40) R69.2(N2) TP18.1(P1)
DPP_CMP_PWM: R85.1(N1) U12.B7(CMP_PWM)
DPP_PLLI: C111.2(N) R101.1(N1) U12.K15(PLL_REFCLK_I) XD100.3(N)
DPP_PLLO: R101.2(N2) R102.1(N1) U12.J15(PLL_REFCLK_O)
DPP_SPICLK: R78.2(N2) U12.A4(SPICLK)
DPP_SPICSZ0: R76.2(N2) U12.A5(SPICSZ0)
DPP_SPICSZ1: R75.2(N2) U12.C6(SPICSZ1)
DPP_SPIDOUT: R77.2(N2) U12.C5(SPIDOUT)
FLEX_TP: JLEDFLEX.5(P5) TP26.1(P1)
FLSH_1P8V: C123.1(P) R103.2(N2) U3.3(/WP) U3.7(/HOLD) U3.8(VCC)
G[0]: P1.13(P13) U12.D15(PDATA_8)
G[1]: P1.12(P12) U12.D14(PDATA_9)
G[2]: P1.42(P42) U12.C15(PDATA_10)
G[3]: P1.39(P39) U12.C14(PDATA_11)
G[4]: P1.40(P40) U12.C13(PDATA_12)
G[5]: P1.37(P37) U12.B15(PDATA_13)
G[6]: P1.38(P38) U12.B14(PDATA_14)
G[7]: P1.36(P36) U12.A15(PDATA_15)
GPIO1_RPWM: TP7.1(P1) U12.N8(GPIO1_RPWM)
GPIO2_GPWM: TP5.1(P1) U12.P9(GPIO2_GPWM)
GPIO3_BPWM: TP4.1(P1) U12.R8(GPIO3_BPWM)
GPIO4: P1.26(P26) U8.2(A) U12.C9(GPIO4_INTF)
GPIO5: P1.18(P18) U12.B9(GPIO5_INTF)
GRN_CATHODE: JLEDFLEX.7(P7) JLEDFLEX.8(P8) TP30.1(P1) U5.G6(SW5)
HOST_PRESENTZ: P2.43(P43) R97.1(N1) U10.3(B) U11.3(ON)
HSYNC: P1.29(P29) U12.H13(HSYNC_CS)
HWTEST_EN: R72.1(N1) U12.A9(HWTEST_EN)
JTAG_TCK: TP13.1(P1) U12.N5(JTAGTCK)
JTAG_TDI: TP11.1(P1) U12.P6(JTAGTDI)
JTAG_TDO: TP8.1(P1) U12.R7(JTAGTDO)
JTAG_TMS: TP10.1(P1) U12.N7(JTAGTMS)
JTAGTRSTZ: R23.2(N2) TP12.1(P1) U12.P8(JTAGTRSTZ)
L1: L3.2 U5.B1(L1_1) U5.B2(L1_2)
L2: L3.1 U5.D1(L2_1) U5.D2(L2_2)
LED_ANODE: C26.1(P) C34.1(P) C35.1(P) JLEDFLEX.1(P1) JLEDFLEX.2(P2) TP28.1(P1) U5.E1(VLED_1) U5.E2(VLED_2) U5.F2(VLED_3) U5.G1(SW1) U5.G2(SW2) U5.G3(SW3)
LED_ENABLE: R70.2(N2) U12.A11(LED_ENABLE)
LED_SEL_0: U5.F3(LED_SEL0) U12.R6(LED_SEL_0)
LED_SEL_1: U5.E3(LED_SEL1) U12.N6(LED_SEL_1)
LEDDRV_ON: TP9.1(P1) U12.P7(LEDDRV_ON)
MEM0_A0: R31.1(N1) U13.J8(A0)
MEM0_A1: R30.1(N1) U13.J9(A1)
MEM0_A2: R26.1(N1) U13.K7(A2)
MEM0_A3: R25.1(N1) U13.K8(A3)
MEM0_A4: R79.1(N1) U13.K2(A4)
MEM0_A5: R59.1(N1) U13.K3(A5)
MEM0_A6: R80.1(N1) U13.J1(A6)
MEM0_A7: R64.1(N1) U13.J2(A7)
MEM0_A8: R62.1(N1) U13.J3(A8)
MEM0_A9: R81.1(N1) U13.H1(A9)
MEM0_A10: R32.1(N1) U13.J7(A10)
MEM0_A11: R82.1(N1) U13.H2(A11)
MEM0_A12: R63.1(N1) U13.H3(A12)
MEM0_A13: R100.1(N1) U13.F7(A13)
MEM0_BA0: R40.1(N1) U13.H8(BA0)
MEM0_BA1: R27.1(N1) U13.H9(BA1)
MEM0_CASZ: R24.1(N1) U13.G8(C\A\S\)
MEM0_CKE: R57.1(N1) U13.G1(CKE)
MEM0_CLK_N: R55.1(N1) R67.1(N1) U13.G3(C\K\)
MEM0_CLK_P: R56.1(N1) R67.2(N2) U13.G2(CK)
MEM0_CSZ: R28.1(N1) U13.H7(C\S\)
MEM0_DQ0: R35.1(N1) U12.N1(MEM0_DQ0)
MEM0_DQ1: R50.1(N1) U12.M2(MEM0_DQ1)
MEM0_DQ2: R33.1(N1) U12.M1(MEM0_DQ2)
MEM0_DQ3: R46.1(N1) U12.L3(MEM0_DQ3)
MEM0_DQ4: R51.1(N1) U12.L2(MEM0_DQ4)
MEM0_DQ5: R47.1(N1) U12.K2(MEM0_DQ5)
MEM0_DQ6: R45.1(N1) U12.L1(MEM0_DQ6)
MEM0_DQ7: R41.1(N1) U12.K1(MEM0_DQ7)
MEM0_DQ8: R49.1(N1) U12.H2(MEM0_DQ8)
MEM0_DQ9: R54.1(N1) U12.G2(MEM0_DQ9)
MEM0_DQ10: R53.1(N1) U12.H3(MEM0_DQ10)
MEM0_DQ11: R65.1(N1) U12.F3(MEM0_DQ11)
MEM0_DQ12: R44.1(N1) U12.F1(MEM0_DQ12)
MEM0_DQ13: R66.1(N1) U12.E2(MEM0_DQ13)
MEM0_DQ14: R60.1(N1) U12.F2(MEM0_DQ14)
MEM0_DQ15: R61.1(N1) U12.E3(MEM0_DQ15)
MEM0_LDM: R42.1(N1) U13.F8(LDM)
MEM0_LDQS: R52.1(N1) U12.J2(MEM0_LDQS)
MEM0_RASZ: R34.1(N1) U13.G9(R\A\S\)
MEM0_UDM: R48.1(N1) U13.F2(UDM)
MEM0_UDQS: R43.1(N1) U12.G1(MEM0_UDQS)
MEM0_WEZ: R29.1(N1) U13.G7(W\E\)
MEM_T_A0: R31.2(N2) U12.P1(MEM0_A0)
MEM_T_A1: R30.2(N2) U12.R3(MEM0_A1)
MEM_T_A2: R26.2(N2) U12.R1(MEM0_A2)
MEM_T_A3: R25.2(N2) U12.R2(MEM0_A3)
MEM_T_A4: R79.2(N2) U12.A1(MEM0_A4)
MEM_T_A5: R59.2(N2) U12.B1(MEM0_A5)
MEM_T_A6: R80.2(N2) U12.A2(MEM0_A6)
MEM_T_A7: R64.2(N2) U12.B2(MEM0_A7)
MEM_T_A8: R62.2(N2) U12.D2(MEM0_A8)
MEM_T_A9: R81.2(N2) U12.A3(MEM0_A9)
MEM_T_A10: R32.2(N2) U12.P2(MEM0_A10)
MEM_T_A11: R82.2(N2) U12.B3(MEM0_A11)
MEM_T_A12: R63.2(N2) U12.D3(MEM0_A12)
MEM_T_BA0: R40.2(N2) U12.M3(MEM0_BA0)
MEM_T_BA1: R27.2(N2) U12.P3(MEM0_BA1)
MEM_T_CASZ: R24.2(N2) U12.R4(MEM0_CASZ)
MEM_T_CKE: R57.2(N2) R58.2(N2) U12.C1(MEM0_CKE)
MEM_T_CLK_N: R55.2(N2) U12.E1(MEM0_CLK_N)
MEM_T_CLK_P: R56.2(N2) U12.D1(MEM0_CLK_P)
MEM_T_CSZ: R28.2(N2) U12.J3(MEM0_CSZ)
MEM_T_DQ0: R35.2(N2) U13.A8(DQ0)
MEM_T_DQ1: R50.2(N2) U13.B7(DQ1)
MEM_T_DQ2: R33.2(N2) U13.B8(DQ2)
MEM_T_DQ3: R46.2(N2) U13.C7(DQ3)
MEM_T_DQ4: R51.2(N2) U13.C8(DQ4)
MEM_T_DQ5: R47.2(N2) U13.D7(DQ5)
MEM_T_DQ6: R45.2(N2) U13.D8(DQ6)
MEM_T_DQ7: R41.2(N2) U13.E7(DQ7)
MEM_T_DQ8: R49.2(N2) U13.E3(DQ8)
MEM_T_DQ9: R54.2(N2) U13.D2(DQ9)
MEM_T_DQ10: R53.2(N2) U13.D3(DQ10)
MEM_T_DQ11: R65.2(N2) U13.C2(DQ11)
MEM_T_DQ12: R44.2(N2) U13.C3(DQ12)
MEM_T_DQ13: R66.2(N2) U13.B2(DQ13)
MEM_T_DQ14: R60.2(N2) U13.B3(DQ14)
MEM_T_DQ15: R61.2(N2) U13.A2(DQ15)
MEM_T_LDM: R42.2(N2) U12.J1(MEM0_LDM)
MEM_T_LDQS: R52.2(N2) U13.E8(LDQS)
MEM_T_RASZ: R34.2(N2) U12.P4(MEM0_RASZ)
MEM_T_UDM: R48.2(N2) U12.H1(MEM0_UDM)
MEM_T_UDQS: R43.2(N2) U13.E2(UDQS)
MEM_T_WEZ: R29.2(N2) U12.R5(MEM0_WEZ)
P1P0V: C2.1(P) C13.1(P) C14.1(P) C104.1(P) C105.1(P) C106.1(P) C107.1(P) C108.1(P) C109.1(P) C110.1(P) F101.1(N1) L1.2 R2.2(N2) TP2.1(P1) U12.D5(VDD#D5) U12.D9(VDD#D9) U12.F4(VDD#F4) U12.F12(VDD#F12) U12.J4(VDD#J4) U12.J12(VDD#J12) U12.M6(VDD#M6) U12.M8(VDD#M8) U12.M11(VDD#M11)
P1P0V_FB: R1.1(N1) R2.1(N1) U1.4(FB)
P1P0V_SW: L1.1 U1.5(SW)
P1P8V: C3.1(P) C4.1(P) C5.1(P) C6.1(P) C7.1(P) C10.1(P) C15.1(P) C16.1(P) C17.1(P) C24.1(P) C100.1(P) C101.1(P) C102.1(P) C103.1(P) C112.1(P) C113.1(P) C114.1(P) C115.1(P) C116.1(P) C117.1(P) C126.1(P) C128.1(P) C130.1(P) J1.1(P1) J1.2(P2) J1.21(P21) J1.22(P22) J1.41(P41) J1.42(P42) L2.2 R70.1(N1) R71.2(N2) R84.2(N2) R103.1(N1) R104.1(N1) R108.2(N2) R109.2(N2) R110.1(N1) R116.1(N1) TP23.1(P1) U5.B5(VSPI) U11.4(VIN#4) U11.6(VIN#6) U12.C4(VCC_18#C4) U12.D6(VCC_FLSH) U12.D8(VCC_18#D8) U12.E4(VCC_18#E4) U12.G3(VCC_18#G3) U12.K3(VCC_18#K3) U12.K12(VCC_18#K12) U12.L4(VCC_18#L4) U12.M5(VCC_18#M5) U12.M9(VCC_18#M9) U12.M12(VCC_18#M12) U12.N4(VCC_18#N4) U12.N12(VCC_18#N12) U13.A7(VDDQ#A7) U13.A9(VDD#A9) U13.B1(VDDQ#B1) U13.C9(VDDQ#C9) U13.D1(VDDQ#D1) U13.E9(VDDQ#E9) U13.F9(VDD#F9) U13.K9(VDD#K9)
P1P8V_FB: R83.1(N1) R84.1(N1) U2.4(FB)
P1P8V_SW: L2.1 U2.5(SW)
P2P5V: C44.1(P) C132.1(P) C134.1(P) D2.2(P2) R90.1(N1) R95.2(N2) U6.5(VCC) U7.5(OUT) U8.5(PWR)
PARKZ: R116.2(N2) U5.B4(INTZ) U12.B8(PARKZ)
PCLK: P1.28(P28) U12.D13(PCLK)
PDM_CVS_TE: TP15.1(P1) U12.H15(PDM_CVS_TE)
PROJ_ON: U5.E6(PROJ_ON) U6.2(A) U10.4(Y)
PROJ_ON_EXT: P2.15(P15) U10.1(A)
PROJ_ON_S/A: U9.2(R\E\S\E\T\) U10.6(C)
PWM_IN: R87.2(N2) U5.D5(PWM_IN)
PWR_EN: U1.3(EN) U2.3(EN) U5.D3(PWR_EN)
PWR_SUPERVISOR: R125.1(N1) U9.3(VDD)
R[0]: P1.14(P14) U12.A14(PDATA_16)
R[1]: P1.11(P11) U12.B13(PDATA_17)
R[2]: P1.15(P15) U12.A13(PDATA_18)
R[3]: P1.45(P45) U12.C12(PDATA_19)
R[4]: P1.46(P46) U12.B12(PDATA_20)
R[5]: P1.43(P43) U12.A12(PDATA_21)
R[6]: P1.44(P44) U12.C11(PDATA_22)
R[7]: P1.41(P41) U12.B11(PDATA_23)
RED_CATHODE: JLEDFLEX.3(P3) JLEDFLEX.4(P4) TP29.1(P1) U5.G5(SW4)
REF_VRST: R93.2(N2) U5.B6(REF_VRST)
RESETZ: TP24.1(P1) U5.B3(RESETZ) U12.J14(RESETZ)
RLIM: R92.1(N1) U5.F5(RLIM_K) U5.F6(RLIM_1) U5.F7(RLIM_2)
RTSZ: R90.2(N2) U5.F4(RSTZ)
S_STAT_LED: D2.1(P1) R129.1(N1)
S_STAT_LEDDRV: R129.2(N2) U8.4(Y)
SBPWR_FB: R94.2(N2) R95.1(N1) U7.1(FB/NC)
SBPWR_IN: C133.1(P) R128.1(N1) U7.4(IN)
SCL: P2.19(P19) R119.1(N1) U4.6(SCL) U12.A10(DBIC_SCL)
SDA: P2.20(P20) R118.1(N1) U4.5(SDA) U12.C10(DBIC_SDA)
SEL_A0: J5.2 R123.1(N1) U4.1(A0)
SEL_A1: J4.2 R122.1(N1) U4.2(A1)
SEL_A2: R121.1(N1) U4.3(A2)
SENS1: TP32.1(P1) U5.E4(SENS1)
SENS2: C37.1(P) R91.2(N2) U5.E5(SENS2)
SPICLK: R78.1(N1) R111.2(N2) U3.6(CLK) U5.C3(SPI_CLK)
SPICSZ0: R76.1(N1) R104.2(N2) U3.1(/CS)
SPICSZ1: R75.1(N1) R110.2(N2) U5.C4(SPI_CSZ)
SPIMISO: R112.2(N2) U3.2(DO) U5.C6(SPI_DOUT) U12.B4(SPIDIN)
SPIMOSI: R77.1(N1) U3.5(DI) U5.C5(SPI_DIN)
STAT_DRV: R126.2(N2) U6.4(Y)
STAT_LED: D3.2(P2) R126.1(N1)
SWN: D1.1(P1) L4.2 U5.A5(SWN)
SWP: L4.1 U5.A7(SWP)
SYSPWR: C1.2(N) C8.2(N) C9.2(N) C11.2(N) C12.2(N) C18.2(N) C19.2(N) C20.2(N) C21.2(N) C23.2(N) C28.1(P) C29.1(P) C30.1(P) C31.1(P) C32.1(P) C41.1(P) C43.1(P) C129.1(P) J2.1(PIN) J3.1 R96.2(N2) R97.2(N2) R117.1(N1) R124.1(N1) R125.2(N2) R128.2(N2) U1.1(VIN) U2.1(VIN) U5.A1(VINL_1) U5.A2(VINL_2) U5.A4(VINR)
SYSPWR_SHUNT: J2.3(SHUNT) R124.2(N2)
THERMISTOR_P: R89.1(N1) R91.1(N1) RT1.1 TP33.1(P1)
TSTPT_0: TP25.1(P1) U12.B6(TXD_TSTPT_0)
TSTPT_1: TP21.1(P1) U12.A8(GPO0_TSTPT_1)
TSTPT_2: TP19.1(P1) U12.C7(GPO1_TSTPT_2)
TSTPT_3: TP27.1(P1) U12.B5(GPO2_TSTPT_3)
TSTPT_4: TP22.1(P1) U12.A7(GPO3_TSTPT_4)
TSTPT_5: TP20.1(P1) U12.C8(GPO4_TSTPT_5)
TSTPT_6: TP6.1(P1) U12.N9(IRW_EN_TSTPT_6)
TSTPT_7: TP3.1(P1) U12.R9(IRW_SYNC_TSTPT_7)
VBIAS: C40.1(P) R68.1(N1) U5.B7(VBIAS)
VOFS: C39.1(P) R107.1(N1) U5.C7(VOFS)
VRST: C42.1(P) D1.2(P2) R69.1(N1) R93.1(N1)
VSYNC: P1.27(P27) U12.H14(VSYNC_WE)
X_OUT1: C122.1(P) R102.2(N2) XD100.1(P)
N16791220: R96.1(N1) U10.5(VCC)
N16866908: R120.1(N1) U4.7(WP)

Pads without a net: J1 39; P1 3 4 5 6 7 8 9 10 20 21 22 23 24 25; P2 4 5 6 7 8 9 10 11 12 13 14 16 17 18 21 22 23 24 25 26 27 28 29 30 31 32 33 34 35 36 37 38 39 40 41 42; U7 3; U8 1; U12 C2 C3 K14 N2 N3; U13 F3; XD100 2 4

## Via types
v1: diameter 0.254, hole 0.102, TOP to LY2, 61 vias
v2: diameter 0.457, hole 0.203, TOP to BOTTOM, 320 vias
v3: diameter 0.254, hole 0.102, LY2 to LY3, 48 vias
v4: diameter 0.254, hole 0.102, TOP to LY3, 221 vias
v5: diameter 0.483, hole 0.229, TOP to BOTTOM, 12 vias
v6: diameter 0.508, hole 0.254, TOP to BOTTOM, 17 vias
v7: diameter 0.406, hole 0.203, TOP to BOTTOM, 1 via

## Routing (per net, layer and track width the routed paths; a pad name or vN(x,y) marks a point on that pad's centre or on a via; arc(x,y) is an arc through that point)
DGND: length 297.8
  TOP w0.203: J1.33 v2(22.58,30.66) ; U5.D6 U5.D7 65.65,18.79 v1(65.49,18.63) ; J1.5 v1(20.24,37.66) ; U5.A3 66.93,20.87 66.98,20.87 67.25,21.14 67.25,21.3 67.4,21.44 v1(67.4,21.66) ; U5.C2 v1(66.05,21.58) ; J1.37 v2(22.58,29.66)
  TOP w0.229: J1.36 v2(15.54,30.16) ; v2(15.54,30.16) 16.04,29.66 J1.38 ; v2(15.54,30.16) 16.04,30.66 J1.34 ; J1.6 v2(15.77,37.66) ; 22.58,36.04 22.58,35.59 22.16,35.16 J1.15 ; 22.58,36.04 22.6,36.07 22.6,36.39 22.33,36.66 J1.9 ; 22.58,36.04 v2(22.58,36.06) ; J1.18 v2(15.75,34.66) ; J1.45 v2(22.6,27.66) ; J1.10 v2(15.76,36.66) ; J1.28 v2(15.76,32.16) ; v2(20.19,31.65) 20.19,32.03 20.83,32.66 J1.25 ; J1.49 v2(22.6,26.66)
  TOP w0.254: v2(16.83,26.14) J1.50 ; JLEDFLEX.6 v2(40.77,19.08) ; v2(26.42,35.59) 26.45,35.59 26.47,35.61 26.47,35.92 26.54,35.99 C13.2 C14.2
  TOP w0.3: U13.F1 v6(54.71,35.51) ; U13.A1 v6(50.71,35.51) ; v2(57.91,35.6) U13.K1 ; v6(52.49,35.54) 52.31,35.71 U13.C1 ; v6(44.71,36.08) 44.97,35.82 ; v2(51.59,43.23) 51.51,43.15 U13.B9 ; U13.D9 v2(53.11,43.23) ; U13.E1 v6(53.91,35.51) ; U13.A3 v6(49.99,37.79)
  TOP w0.305: v2(41.58,35.23) 41.56,35.21 R58.1 ; C3.2 50.06,44.95 49.75,45.26 v6(49.75,45.26) ; v6(48.83,42.21) 48.83,42.2 C10.2 ; C7.2 59.75,43.73 v2(59.77,43.74) ; C4.2 v6(51.68,45.16) ; C15.2 v2(50.56,34.29) ; v6(55.85,33.27) 55.02,32.44 46.61,32.44 v6(43.54,35.51) ; v6(53.91,35.51) 53.92,35.5 53.92,34.9 53.81,34.78 C16.2 53.81,33.87 53.52,33.58 47.21,33.58 44.97,35.82
  TOP w0.381: v2(15.77,37.66) 15.12,37.66 C126.2 ; v2(43.23,11.94) 43.24,11.93 R94.1 ; C27.1 v2(64.06,24.82) ; C40.2 66.92,14.98 v2(67.12,14.77) ; v2(17.5,25.12) 18.01,24.61 J1.52 ; C23.1 28.12,24.8 28.32,25.01 U2.2 v2(30.53,25.01) R83.2 ; v2(28.88,17.92) 28.89,17.91 U4.4 ; R74.1 33.07,30.16 v2(33.07,29.2) ; U6.3 43.11,10.56 v2(43.12,10.57) ; v2(12.5,43.99) 12.5,46.28 13.07,46.85 C2.2 ; v2(12.5,43.99) U1.2 10.29,43.99 10.08,43.79 C1.1 ; v2(12.5,43.99) R1.2 ; C24.2 33.8,27.86 33.67,27.73 32.97,27.73 v2(32.87,27.63) ; C6.2 v6(55.33,45.16) ; C39.2 v2(65.96,15.99) ; v2(61.28,20.5) 61.41,20.5 61.41,20.52 61.86,20.07 C36.1 ; v2(61.14,17.8) 61.5,18.16 C37.2 ; v2(21.72,41.71) 21.06,41.71 20.06,40.71 J1.51 ; D3.1 v2(38.35,8.13) ; v5(19.75,19.42) 19.75,18.71 C32.2 20.89,18.71 v5(20.89,19.42) ; C35.2 v2(60.08,21.34) 59.7,20.95 C33.2 ; U3.4 49.29,25.78 v2(49.3,25.77) ; R23.1 v2(35.81,45.61) ; U10.2 v2(59.41,6.86) ; C34.2 v2(60.08,22.61) ; v2(55.55,8.72) 55.56,8.71 U9.1 ; U6.1 43.03,9.26 v2(43.04,9.25) ; C38.2 v2(65.01,15.98) ; v5(19.75,7.92) 19.75,8.64 C43.2 20.89,8.64 v5(20.89,7.92) ; C42.2 v2(71.87,19.95) ; C31.2 v2(72.25,23.56) ; U11.2 v2(64.77,9.96) ; C26.2 v2(60.08,23.88) ; C5.2 v6(53.31,45.16) ; U7.2 v2(44.41,9.7) ; v2(59,36.07) 59.09,36.15 C17.2 ; C41.2 v2(69.96,21.78) ; RT1.2 58.93,18.16 v2(58.5,17.73) ; v2(49.81,8.38) 49.82,8.39 U8.3 ; C28.2 v2(72.25,27.37) ; U11.5 v2(64.77,12.59) ; C25.2 v2(56.82,22.86) ; C29.2 v2(72.25,26.1) ; R92.2 v2(63.21,16.1) ; C44.2 v2(48.78,12.67) ; C30.2 v2(72.25,24.83) ; R72.2 v2(31.81,32.15)
  LY2 w0.102: 32.72,37.8 32.71,37.79 v1(32.71,37.53) ; 33.27,38.02 33.77,37.53 v1(33.91,37.53) ; v1(33.91,40.73) v1(33.91,39.93)
  LY2 w0.381: 25.78,10.4 J5.1 ; J5.1 25.78,12.19 ; J5.1 27.56,10.4 ; J5.1 27.56,12.19 ; P2.45 66.26,2.71 ; P2.45 64.65,1.1 ; P2.45 64.65,2.71 ; P2.2 10.38,5.25 ; P2.2 8.77,3.64 ; P2.2 10.38,3.64 ; P2.2 8.77,5.25 ; 15.62,11.87 J3.2 ; J3.2 17.4,10.08 ; J3.2 15.62,10.08 ; J3.2 17.4,11.87 ; J4.1 24.71,10.4 ; J4.1 22.92,12.19 ; J4.1 24.71,12.19 ; J4.1 22.92,10.4 ; P2.1 10.38,2.71 ; P2.1 8.77,1.1 ; P2.1 10.38,1.1 ; P2.1 8.77,2.71 ; 8.77,53.51 P1.2 ; P1.2 8.77,51.9 ; P1.2 10.38,53.51 ; P1.2 10.38,51.9 ; 70.49,11.62 TPGND2.1 ; TPGND2.1 71.75,12.87 ; TPGND2.1 70.49,12.87 ; TPGND2.1 71.75,11.62 ; TPGND1.1 16.82,7.79 ; TPGND1.1 15.57,7.79 ; TPGND1.1 15.57,6.54 ; TPGND1.1 16.82,6.54 ; P1.1 10.38,50.97 ; P1.1 10.38,49.36 ; P1.1 8.77,49.36 ; P1.1 8.77,50.97 ; 5.51,15.72 J2.2 ; J2.2 7.9,15.72 ; J2.2 7.9,11.3 ; J2.2 5.51,11.3 ; P2.46 66.26,5.25 ; P2.46 66.26,3.64 ; P2.46 64.65,3.64 ; P2.46 64.65,5.25 ; P2.44 63.72,3.64 ; P2.44 62.11,5.25 ; P2.44 63.72,5.25 ; P2.44 62.11,3.64
  LY3 w0.152: v2(32.36,39.12) 32.15,38.91 31.27,38.91 31.09,38.73 v4(30.71,38.73) ; v4(31.51,37.53) 31.51,37.57 31.25,37.83 30.98,37.83 30.8,37.65 30.8,37.62 v4(30.71,37.53)
  LY5 w0.381: P2.2 10.38,3.64 ; P2.2 8.77,3.64 ; P2.2 10.38,5.25 ; P2.2 8.77,5.25 ; TPGND1.1 16.82,7.79 ; TPGND1.1 15.57,6.54 ; TPGND1.1 16.82,6.54 ; TPGND1.1 15.57,7.79 ; P2.44 63.72,5.25 ; P2.44 63.72,3.64 ; P2.44 62.11,3.64 ; P2.44 62.11,5.25 ; 8.77,50.97 P1.1 ; P1.1 10.38,49.36 ; P1.1 8.77,49.36 ; P1.1 10.38,50.97 ; 22.92,10.4 J4.1 ; J4.1 22.92,12.19 ; J4.1 24.71,10.4 ; J4.1 24.71,12.19 ; P2.46 66.26,5.25 ; P2.46 66.26,3.64 ; P2.46 64.65,5.25 ; P2.46 64.65,3.64 ; J3.2 17.4,11.87 ; J3.2 17.4,10.08 ; J3.2 15.62,10.08 ; J3.2 15.62,11.87 ; P1.2 10.38,53.51 ; P1.2 8.77,51.9 ; P1.2 10.38,51.9 ; P1.2 8.77,53.51 ; TPGND2.1 71.75,12.87 ; TPGND2.1 70.49,11.62 ; TPGND2.1 70.49,12.87 ; TPGND2.1 71.75,11.62 ; 5.51,11.3 J2.2 ; J2.2 7.9,11.3 ; J2.2 5.51,15.72 ; J2.2 7.9,15.72 ; 25.78,12.19 J5.1 ; J5.1 27.56,10.4 ; J5.1 27.56,12.19 ; J5.1 25.78,10.4 ; P2.1 10.38,1.1 ; P2.1 8.77,1.1 ; P2.1 10.38,2.71 ; P2.1 8.77,2.71 ; 64.65,2.71 P2.45 ; P2.45 66.26,2.71 ; P2.45 64.65,1.1
  BOTTOM w0.254: C119.2 30.24,35.22 v2(29.76,34.73) ; v2(26.55,38.23) 26.49,38.23 24.33,36.07 22.61,36.07 22.6,36.06 v2(22.58,36.06) 22.57,36.06 22.56,36.07 20.37,36.07 19.61,36.83 19.61,40.87 20.45,41.71 v2(21.72,41.71) 23.16,41.71 24.08,40.79 27.56,40.79 28.39,39.96 C110.2 C108.2 C106.2
  BOTTOM w0.305: R100.2 v2(56.64,40.39)
  BOTTOM w0.381: v2(69.44,18.75) 69.44,19.01 C130.2 ; C123.2 v2(53.02,29.59) ; C124.2 v2(18.16,31.17) ; C125.2 v2(18.16,29.16) ; C132.2 50.71,10.86 v2(50.49,11.08) ; R112.1 v2(49.25,28.32) ; C131.2 v2(24.33,20.93) ; C134.2 41.08,8.97 v2(41.54,8.52) ; v2(46.86,9.7) 46.53,9.37 C133.2 ; R111.1 v2(53.02,27.05) ; C111.1 24.66,37.99 v2(24.72,37.93) ; C122.2 20.46,39.2 v7(20.07,39.6) 19.61,39.6 19.61,39.6 ; C127.2 v2(20.19,31.65) ; v2(69.96,21.78) C41.2 ; F100.2 v2(26.55,38.23)
  BOTTOM w0.508: C128.2 v2(17.5,26.06)
  vias: v1(30.71,40.33) v1(31.51,40.73) v1(32.71,40.73) v1(33.91,39.13) v1(33.91,38.73) v1(66.85,19.58) v2(9.21,46.85) v2(25.91,44.32) v2(26.64,44.33) v2(34.36,44.65) v2(34.34,43.84) v2(35.81,43.94) v2(35.85,44.75) v2(60.01,46.53) v2(62.89,45.33) v2(62.89,44.06) v2(62.89,42.79) v2(62.89,41.52) v2(62.89,40.25) v2(62.89,38.98) v2(62.89,37.71) v2(62.89,36.44) v2(62.89,35.17) v2(62.89,33.9) v2(62.89,32.63) v2(64.96,30.02) v2(69.48,44.95) v2(69.51,44.06) v2(69.51,42.79) v2(69.51,41.52) v2(69.51,40.25) v2(69.51,38.98) v2(69.51,37.71) v2(69.51,36.44) v2(69.51,35.17) v2(69.51,33.9) v2(69.51,32.63) v3(64.58,22.9) v3(65.02,23.31) v3(65.65,22.31) v3(66.45,22.32)
V2V5: length 1.6
  TOP w0.203: C38.1 65.01,18.76 65.25,19 U5.E7
V6V: length 1.8
  TOP w0.203: C27.2 64.06,22.66 64.85,21.87 U5.F1
VDD_PLL: length 5.4
  LY2 w0.102: v2(31.44,38.5) 31.27,38.5 31.17,38.6 31.17,38.98 31.02,39.13 v1(30.71,39.13)
  BOTTOM w0.132: F101.2 29.31,36.7 C121.2 29.87,36.68 C120.1 30.59,37.17 31.06,37.64 31.06,38.13 v2(31.44,38.5)
VINA: length 2.2
  TOP w0.203: U5.G4 64.22,20.38 63.91,20.07 v2(63.61,20.07) C36.2
  BOTTOM w0.132: C36.2 v2(63.61,20.07)
VINTF: length 24.3
  TOP w0.102: v2(32.16,38.43) 32.16,38.27 31.7,37.81 31.39,37.81 31.11,37.53 v4(31.11,37.53) U12.E12
  TOP w0.381: U11.1 61.62,9.04 TP34.1 ; U4.8 25.08,22.86 v2(25.1,22.87)
  LY4 w0.381: TP34.1 62.15,8.51 ; TP34.1 61.04,8.51 ; TP34.1 62.15,9.62 ; TP34.1 61.04,9.62 ; P2.3 12.92,2.71 ; P2.3 11.31,2.71 ; P2.3 12.92,1.1 ; P2.3 11.31,1.1
  BOTTOM w0.254: C118.1 31.51,37.77 v2(32.16,38.43) ; C118.1 C119.1 ; C118.1 31.51,35.76 31.43,35.67 v2(31.43,35.1)
  BOTTOM w0.381: R118.2 v2(28.89,22.85) ; v2(27.63,17.87) 27.62,17.86 R121.2 ; R123.2 v2(25.08,17.87) ; R120.2 v2(26.35,22.85) ; C131.1 25.1,21.98 v2(25.1,22.87) ; R122.2 v2(26.35,17.87) ; R119.2 v2(27.62,22.85)
VSS_PLL: length 5.7
  LY3 w0.102: v4(30.31,39.53) 30.31,39.53 30.59,39.25 31.47,39.25 v2(31.55,39.33)
  BOTTOM w0.132: F100.1 28.36,38.25 C121.1 29.87,38.25 C120.2 30.35,37.77 30.77,38.18 30.77,38.55 v2(31.55,39.33)
B[0]: length 42.2
  LY2 w0.102: v3(29.06,38.56) 29.22,38.73 v1(29.91,38.73)
  LY3 w0.132: v3(29.06,38.56) 28.58,38.56 26.71,36.69 26.71,36.46 25.81,35.57 25.81,35.16 v2(25.81,35.16)
  BOTTOM w0.132: v2(25.81,35.16) 24.25,35.16 23.75,35.66 19.05,35.66 17.39,37.32 17.39,39.2 16,40.59 16,45.12 18.37,47.49 29.76,47.49 P1.19
B[1]: length 41.6
  LY3 w0.102: 28.73,38.28 29.17,38.28 29.62,38.73 v4(30.31,38.73)
  LY3 w0.132: 28.73,38.28 28.65,38.28 26.95,36.58 26.95,35.27 v2(26.39,34.71)
  BOTTOM w0.132: v2(26.39,34.71) 24.25,34.71 24.13,34.83 24.11,34.83 23.61,35.33 18.91,35.33 17.05,37.19 17.05,37.46 17.05,38.93 15.65,40.34 15.65,45.24 18.23,47.82 27.55,47.82 P1.17
B[2]: length 45.9
  TOP w0.132: v2(24.46,32.95) 24.91,33.41 24.91,33.42 25.04,33.55 25.04,36.92 25.95,37.83 27.03,37.83 27.52,38.33 U12.F15
  BOTTOM w0.132: P1.16 25.9,51.25 24.11,51.25 23.62,50.75 23.62,49.68 22.43,48.49 17.84,48.49 14.91,45.57 14.91,36.6 15.28,36.23 17.06,36.23 18.65,34.65 23.29,34.65 23.54,34.4 23.54,33.36 23.69,33.21 23.95,32.95 v2(24.46,32.95)
B[3]: length 43.1
  LY2 w0.102: v1(29.91,38.33) 29.21,38.33 28.85,37.97 v3(28.76,37.97)
  LY3 w0.132: v3(28.76,37.97) 27.22,36.43 v2(27.22,34.37)
  BOTTOM w0.132: P1.34 49.26,53.66 44.74,53.66 43.74,52.66 43.74,49.85 40.28,46.39 40.28,39.69 34.22,33.63 29.48,33.63 28.73,34.37 v2(27.22,34.37)
B[4]: length 45.9
  LY3 w0.102: 29.22,38 29.02,37.81
  LY3 w0.132: v4(30.31,38.33) 29.54,38.33 29.22,38 29.2,38 29.02,37.83 29.02,37.81 27.55,36.34 27.55,34.6 27.61,34.54 27.61,34.21 26.81,33.41 26.7,33.41 26.44,33.15 26.44,32.36 26.8,32 v2(26.82,32)
  BOTTOM w0.132: P1.35 52.61,50.16 51.14,48.69 50.23,48.69 44.45,42.91 44.45,39.24 36.21,31 35.39,31 34.77,30.38 29.14,30.38 28.37,31.16 28.15,31.16 27.31,32 26.85,32 26.82,32.03 v2(26.82,32)
B[5]: length 44.7
  TOP w0.132: U12.E15 27.64,37.93 27.2,37.5 26.09,37.5 25.37,36.78 25.37,33.41 25.25,33.28 25.25,32.43 25.55,32.13 25.74,32.13 25.74,32.14 v2(25.73,32.14)
  BOTTOM w0.132: v2(25.73,32.14) 25.74,32.14 25.74,32.13 25.75,32.15 25.76,32.15 25.76,32.13 26.02,32.4 27.38,32.4 28.29,31.5 29.3,31.5 29.75,31.05 34.49,31.05 43.74,40.3 43.74,43.69 P1.33
B[6]: length 38.8
  LY2 w0.102: v3(29.32,37.71) 29.54,37.93 v1(29.91,37.93)
  LY3 w0.132: v2(26.86,33.01) 27.86,34.01 27.86,34.64 27.8,34.7 27.8,36.19 v3(29.32,37.71)
  BOTTOM w0.132: v2(26.86,33.01) 26.92,33.08 27.3,33.08 27.49,33.27 27.82,33.27 28.27,32.82 28.27,32.46 28.57,32.17 29.58,32.17 30.02,31.72 34.21,31.72 42.27,39.78 42.27,44.75 P1.31
B[7]: length 37.6
  LY3 w0.102: v4(30.31,37.93) 29.74,37.36 29.74,36.79 28.54,35.59
  LY3 w0.132: 28.54,35.59 28.54,35.01 28.6,34.95 28.6,32.7 v2(28.73,32.57)
  BOTTOM w0.132: P1.32 46.33,51.36 46.33,50.01 41.66,45.33 41.66,39.64 34.58,32.57 v2(28.73,32.57)
BLU_CATHODE: length 12.6
  LY3 w0.254: v4(64.45,19.18) 64.42,19.18 63.84,18.6 62.74,18.6
  LY3 w0.508: TP31.1 60.83,16.51 62.29,17.97 62.29,18.15 62.74,18.6
CMP_OUT: length 48
  TOP w0.132: v4(33.73,28.69) 33.53,28.88 33.53,30.75 33.03,31.25 R74.2 33.77,32.01 33.77,33.61 33.87,33.7 33.87,34.51 33.11,35.27 U12.A6
  LY3 w0.132: v4(65.65,20.38) 65.65,20.6 65.35,20.89 64.25,20.89 64.08,21.06 62.46,21.06 62.36,21.16 60.68,21.16 60.42,20.89 56.06,20.89 55.74,20.57 54.2,20.57 53.67,21.11 35.47,21.11 33.99,22.59 33.99,28.43 v4(33.73,28.69)
CMP_PWM_F: length 1.9
  TOP w0.132: R86.1 C25.1 R85.2
CMP_PWM_F2: length 1.9
  TOP w0.132: R86.2 C33.1 R87.1
CMP_PWR: length 58.9
  TOP w0.132: R89.2 v2(57.94,17.21)
  LY2 w0.102: v1(33.51,41.53) 33.51,41.84 33.85,42.18 33.92,42.18 33.92,42.2 v3(33.9,42.2)
  LY3 w0.102: v3(33.9,42.2) 34.31,42.61 34.31,42.67
  LY3 w0.132: v2(59.12,45.3) 57.82,46.6 38.55,46.6 37.02,45.06 37.02,44.44 36.04,43.47 35.11,43.47 34.31,42.67
  BOTTOM w0.132: v2(57.94,17.21) 57.94,18.68 58.26,19 58.26,35.32 58.32,35.38 58.32,36.84 59.12,37.65 v2(59.12,45.3)
